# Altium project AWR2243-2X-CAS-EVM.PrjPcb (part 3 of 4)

## Sheet FE1_IO.schdoc: XDS110 Interface_1B
size 431 x 279 mm; Date: Not shown in title block; ApprovedBy: Not shown in title block; CheckedBy: Not shown in title block; Author: Not shown in title block; CompanyName: Not shown in title block; DrawnBy: B. Shaffer; Engineer: Not shown in title block; Organization: Not shown in title block; Address1: Not shown in title block; Address2: Not shown in title block; Address3: Not shown in title block; Address4: Not shown in title block; DocumentNumber: 7; Revision: Use project parameter SCH_Rev; SheetNumber: 7; SheetTotal: 17; PageSetup: Record=PageOptions¦CenterHorizontal=True¦CenterVertical=True¦PrintScale=1.00¦XCorrection=1.00¦YCorrection=1.00¦PrintKind=0¦BorderSize=5000000¦LeftOffset=0¦BottomOffset=0¦Orientation=2¦PaperLength=1000¦PaperWidth=1000¦Scale=100¦PaperSource=15¦PrintQuality=600¦MediaType=1¦DitherType=10¦PaperKind=Letter¦PrintScaleMode=1
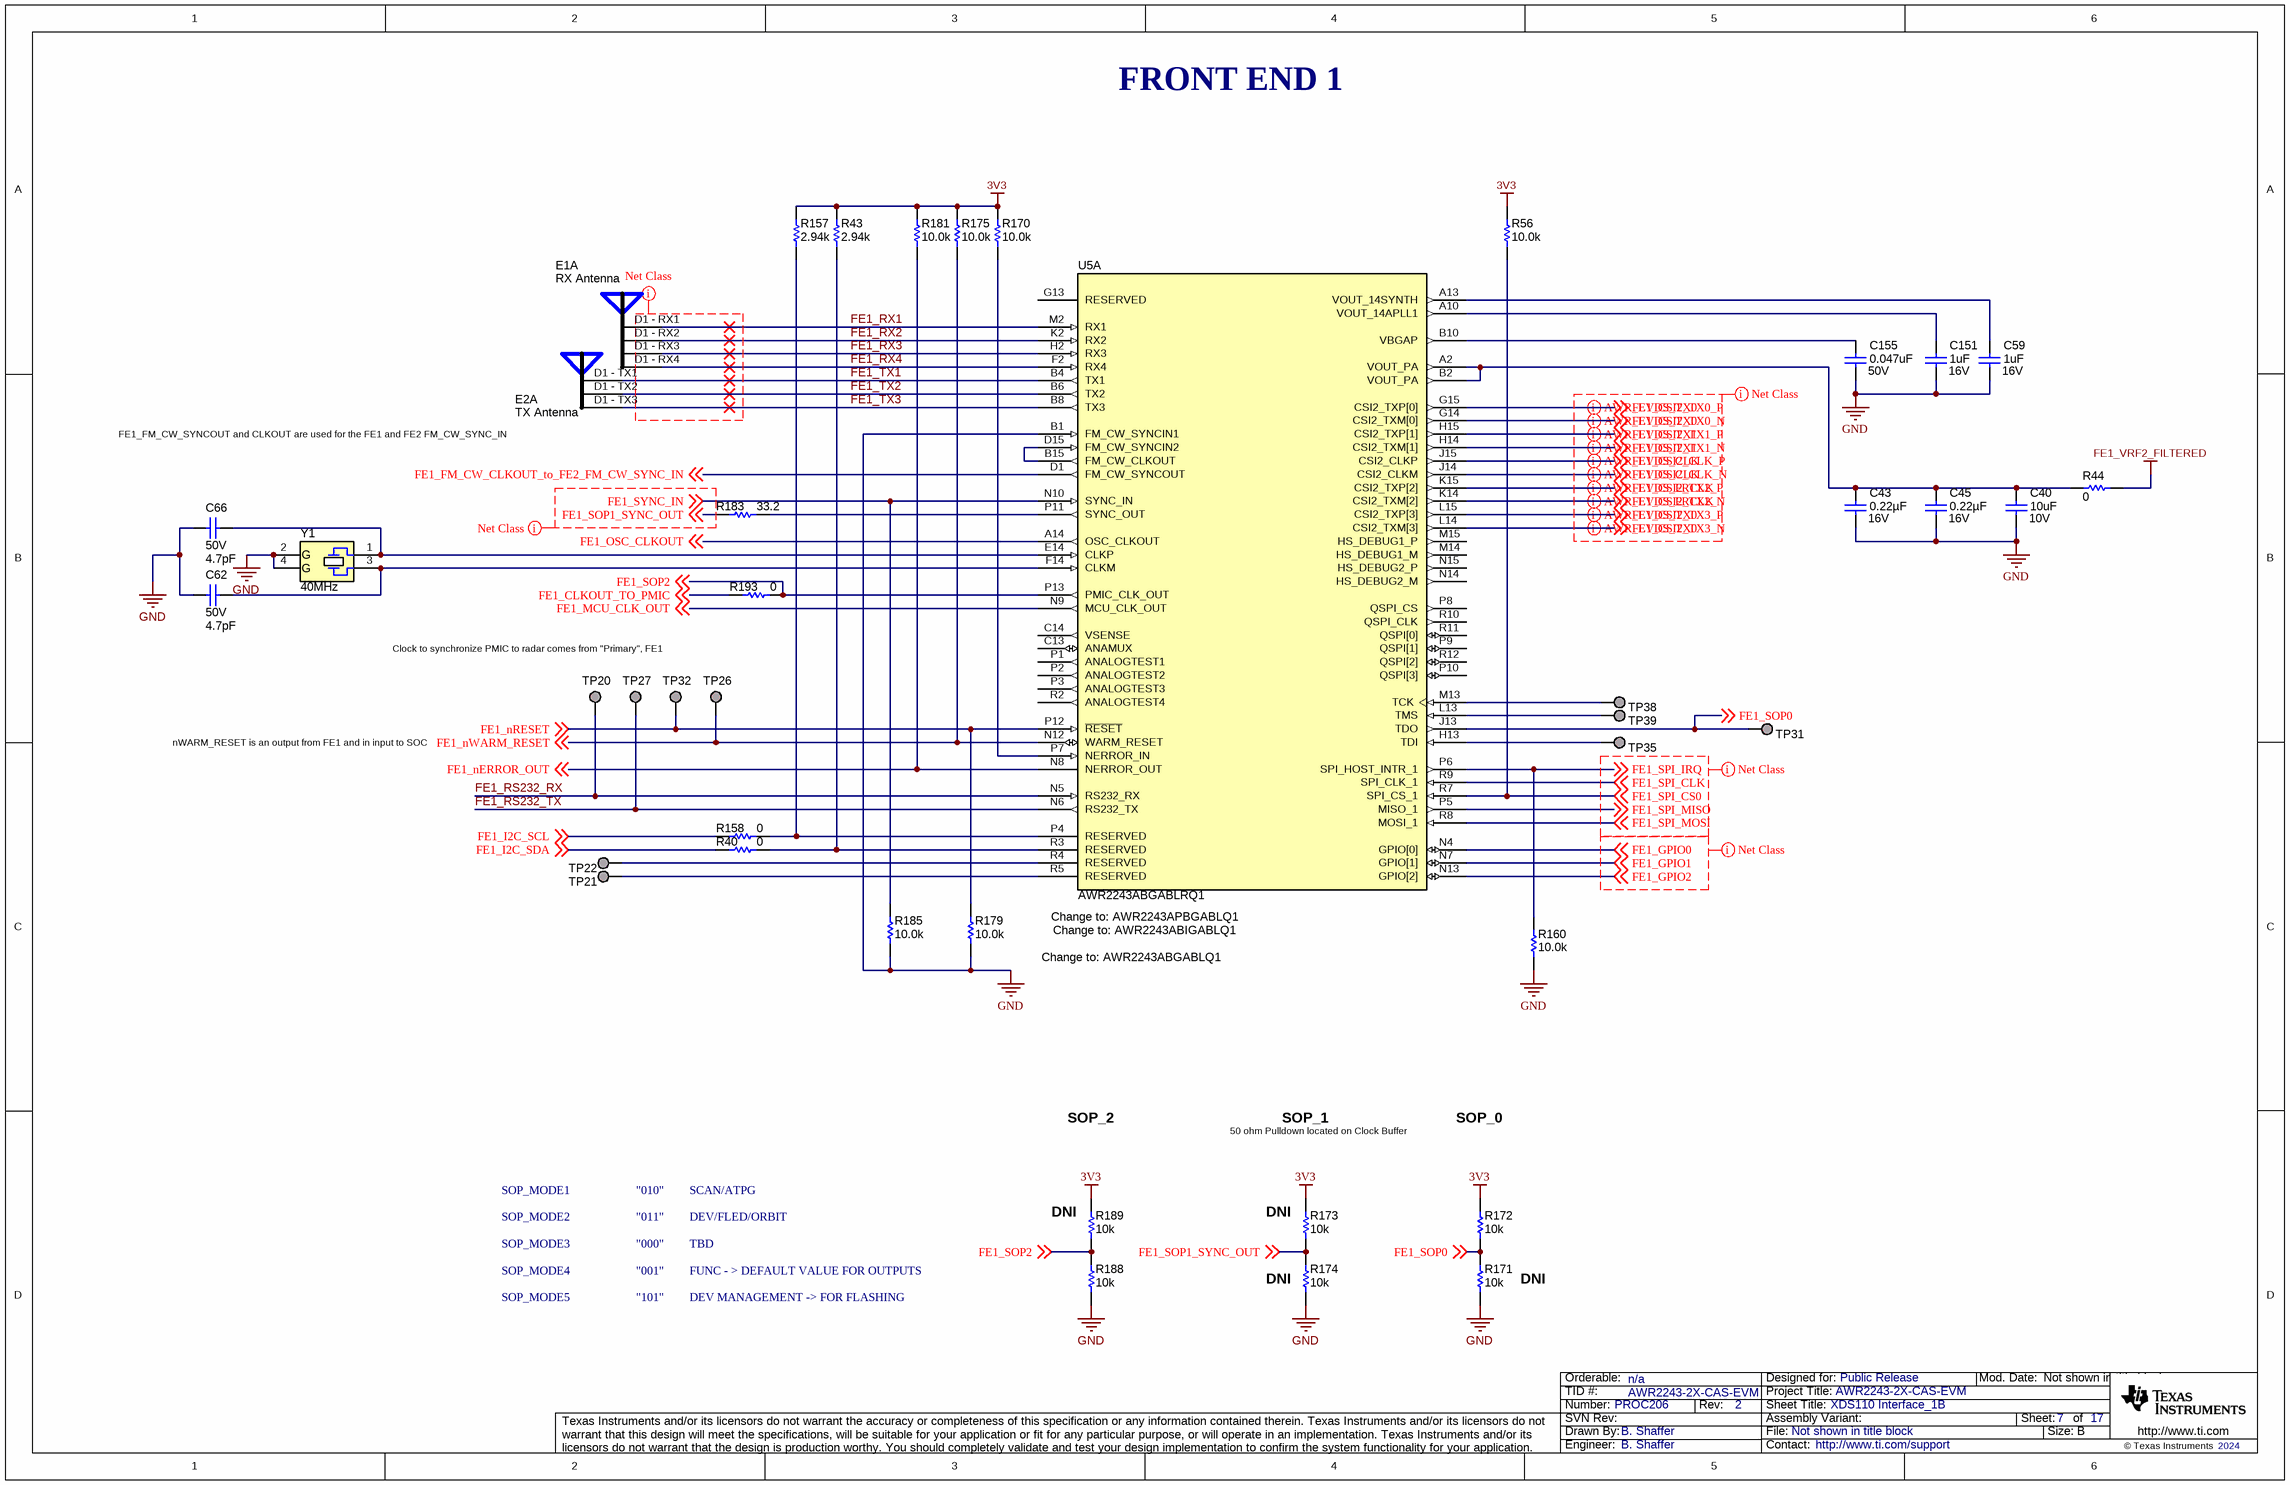
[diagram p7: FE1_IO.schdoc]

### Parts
(Parts that share a designator on the sheet are numbered #1, #2 ... from top to bottom, then left to right.)
C40  VDC_V: 10V  ValueDisplayed: 10uF  [0805_HV]  (hidden comment: GCM21BR71A106KE22L)
C43  VDC_V: 16V  ValueDisplayed: 0.22µF  [0402]  (hidden comment: GCM155R71C224KE02D)
C45  VDC_V: 16V  ValueDisplayed: 0.22µF  [0402L]  (hidden comment: GCM155R71C224KE02D)
C59  VDC_V: 16V  ValueDisplayed: 1uF  [0603]  (hidden comment: GCM188R71C105KA64D)
C62  VDC_V: 50V  ValueDisplayed: 4.7pF  [0402]  (hidden comment: GJM1555C1H4R7BB01D)
C66  VDC_V: 50V  ValueDisplayed: 4.7pF  [0402]  (hidden comment: GJM1555C1H4R7BB01D)
C151  VDC_V: 16V  ValueDisplayed: 1uF  [0603]  (hidden comment: GCM188R71C105KA64D)
C155  VDC_V: 50V  ValueDisplayed: 0.047uF  [0402]  (hidden comment: CGA2B3X7R1H473K050BB)
E1  RX Antenna  [RX Antenna]  (part A of 2)
E2  TX Antenna  [TX Antenna]  (part A of 2)
R40  ValueDisplayed: 0  [0402]  (hidden comment: CRCW04020000Z0ED)
R43  ValueDisplayed: 2.94k  [0402L]  (hidden comment: CRCW04022K94FKED)
R44  ValueDisplayed: 0  [0603]  (hidden comment: MCT06030Z0000ZP500)
R56  ValueDisplayed: 10.0k  [0402L]  (hidden comment: CRCW040210K0FKED)
R157  ValueDisplayed: 2.94k  [0402]  (hidden comment: CRCW04022K94FKED)
R158  ValueDisplayed: 0  [0402]  (hidden comment: CRCW04020000Z0ED)
R160  ValueDisplayed: 10.0k  [0402L]  (hidden comment: CRCW040210K0FKED)
R170  ValueDisplayed: 10.0k  [0402L]  (hidden comment: CRCW040210K0FKED)
R171  ValueDisplayed: 10k  [0402]  (hidden comment: CRCW040210K0JNED)
R172  ValueDisplayed: 10k  [0402]  (hidden comment: CRCW040210K0JNED)
R173  ValueDisplayed: 10k  [0402]  (hidden comment: CRCW040210K0JNED)
R174  ValueDisplayed: 10k  [0402]  (hidden comment: CRCW040210K0JNED)
R175  ValueDisplayed: 10.0k  [0402L]  (hidden comment: CRCW040210K0FKED)
R179  ValueDisplayed: 10.0k  [0402L]  (hidden comment: CRCW040210K0FKED)
R181  ValueDisplayed: 10.0k  [0402L]  (hidden comment: CRCW040210K0FKED)
R183  ValueDisplayed: 33.2  [0402S]  (hidden comment: CRCW040233R2FKED)
R185  ValueDisplayed: 10.0k  [0402L]  (hidden comment: CRCW040210K0FKED)
R188  ValueDisplayed: 10k  [0402]  (hidden comment: CRCW040210K0JNED)
R189  ValueDisplayed: 10k  [0402]  (hidden comment: CRCW040210K0JNED)
R193  ValueDisplayed: 0  [0402]  (hidden comment: CRCW04020000Z0ED)
TP20  TP_H0.45P0.75  [TP_H045P075]  (value not drawn)  (no BOM)
TP21  TP_H0.45P0.75  [TP_H045P075]  (value not drawn)  (no BOM)
TP22  TP_H0.45P0.75  [TP_H045P075]  (value not drawn)  (no BOM)
TP26  TP_H0.45P0.75  [TP_H045P075]  (value not drawn)  (no BOM)
TP27  TP_H0.45P0.75  [TP_H045P075]  (value not drawn)  (no BOM)
TP31  TP_H0.45P0.75  [TP_H045P075]  (value not drawn)  (no BOM)
TP32  TP_H0.45P0.75  [TP_H045P075]  (value not drawn)  (no BOM)
TP35  TP_H0.45P0.75  [TP_H045P075]  (value not drawn)  (no BOM)
TP38  TP_H0.45P0.75  [TP_H045P075]  (value not drawn)  (no BOM)
TP39  TP_H0.45P0.75  [TP_H045P075]  (value not drawn)  (no BOM)
U5#2  AWR2243ABGABLRQ1  [ABL0161A]  (part A of 2)
Y1  Frequency_Fixed: 40MHz  [Kyocera_CX3225SA]  (hidden comment: CX3225SA40000D0PTWCC)

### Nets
3V3: R43.2 R56.2 R157.2 R170.2 R172.2 R173.2 R175.2 R181.2 R189.2
FE1_VRF2_FILTERED: R44.2
GND: C40.2 C43.2 C45.2 C59.2 C62.2 C66.2 C151.2 C155.2 R160.1 R171.1 R174.1 R179.1 R185.1 R188.1 U5#2.B1(FM_CW_SYNCIN1) Y1.2(GND) Y1.4(GND)
FE1_CLKOUT_TO_PMIC: R193.2 ; off-sheet FE1_CLKOUT_TO_PMIC
FE1_CSI2_CLK_N: U5#2.J14(CSI2_CLKM) ; off-sheet FE1_CSI2_CLK_N
FE1_CSI2_CLK_P: U5#2.J15(CSI2_CLKP) ; off-sheet FE1_CSI2_CLK_P
FE1_CSI2_TX0_N: U5#2.G14(CSI2_TXM[0]) ; off-sheet FE1_CSI2_TX0_N
FE1_CSI2_TX0_P: U5#2.G15(CSI2_TXP[0]) ; off-sheet FE1_CSI2_TX0_P
FE1_CSI2_TX1_N: U5#2.H14(CSI2_TXM[1]) ; off-sheet FE1_CSI2_TX1_N
FE1_CSI2_TX1_P: U5#2.H15(CSI2_TXP[1]) ; off-sheet FE1_CSI2_TX1_P
FE1_CSI2_TX2_N: U5#2.K14(CSI2_TXM[2]) ; off-sheet FE1_CSI2_TX2_N
FE1_CSI2_TX2_P: U5#2.K15(CSI2_TXP[2]) ; off-sheet FE1_CSI2_TX2_P
FE1_CSI2_TX3_N: U5#2.L14(CSI2_TXM[3]) ; off-sheet FE1_CSI2_TX3_N
FE1_CSI2_TX3_P: U5#2.L15(CSI2_TXP[3]) ; off-sheet FE1_CSI2_TX3_P
FE1_FM_CW_CLKOUT_to_FE2_FM_CW_SYNC_IN: U5#2.D1(FM_CW_SYNCOUT) ; off-sheet FE1_FM_CW_CLKOUT_to_FE2_FM_CW_SYNC_IN
FE1_GPIO0: U5#2.N4(GPIO[0]) ; off-sheet FE1_GPIO0
FE1_GPIO1: U5#2.N7(GPIO[1]) ; off-sheet FE1_GPIO1
FE1_GPIO2: U5#2.N13(GPIO[2]) ; off-sheet FE1_GPIO2
FE1_I2C_SCL: R158.2 ; off-sheet FE1_I2C_SCL
FE1_I2C_SDA: R40.2 ; off-sheet FE1_I2C_SDA
FE1_MCU_CLK_OUT: U5#2.N9(MCU_CLK_OUT) ; off-sheet FE1_MCU_CLK_OUT
FE1_nERROR_OUT: R181.1 U5#2.N8(NERROR_OUT) ; off-sheet FE1_nERROR_OUT
FE1_nRESET: R179.2 TP32.1 U5#2.P12(~{RESET}) ; off-sheet FE1_nRESET
FE1_nWARM_RESET: R175.1 TP26.1 U5#2.N12(WARM_RESET) ; off-sheet FE1_nWARM_RESET
FE1_OSC_CLKOUT: U5#2.A14(OSC_CLKOUT) ; off-sheet FE1_OSC_CLKOUT
FE1_RS232_RX: TP20.1 U5#2.N5(RS232_RX)
FE1_RS232_TX: TP27.1 U5#2.N6(RS232_TX)
FE1_RX1: E1.D1_-_RX1 U5#2.M2(RX1)
FE1_RX2: E1.D1_-_RX2 U5#2.K2(RX2)
FE1_RX3: E1.D1_-_RX3 U5#2.H2(RX3)
FE1_RX4: E1.D1_-_RX4 U5#2.F2(RX4)
FE1_SOP0: R171.2 R172.1 TP31.1 U5#2.J13(TDO) ; off-sheet FE1_SOP0
FE1_SOP1_SYNC_OUT: R173.1 R174.2 R183.1 ; off-sheet FE1_SOP1_SYNC_OUT
FE1_SOP2: R188.2 R189.1 R193.1 U5#2.P13(PMIC_CLK_OUT) ; off-sheet FE1_SOP2
FE1_SPI_CLK: U5#2.R9(SPI_CLK_1) ; off-sheet FE1_SPI_CLK
FE1_SPI_CS0: R56.1 U5#2.R7(SPI_CS_1) ; off-sheet FE1_SPI_CS0
FE1_SPI_IRQ: R160.2 U5#2.P6(SPI_HOST_INTR_1) ; off-sheet FE1_SPI_IRQ
FE1_SPI_MISO: U5#2.P5(MISO_1) ; off-sheet FE1_SPI_MISO
FE1_SPI_MOSI: U5#2.R8(MOSI_1) ; off-sheet FE1_SPI_MOSI
FE1_SYNC_IN: R185.2 U5#2.N10(SYNC_IN) ; off-sheet FE1_SYNC_IN
FE1_TX1: E2.D1_-_TX1 U5#2.B4(TX1)
FE1_TX2: E2.D1_-_TX2 U5#2.B6(TX2)
FE1_TX3: E2.D1_-_TX3 U5#2.B8(TX3)
NetC40_1: C40.1 C43.1 C45.1 R44.1 U5#2.A2(VOUT_PA) U5#2.B2(VOUT_PA)
NetC59_1: C59.1 U5#2.A13(VOUT_14SYNTH)
NetC62_1: C62.1 U5#2.F14(CLKM) Y1.3
NetC66_1: C66.1 U5#2.E14(CLKP) Y1.1
NetC151_1: C151.1 U5#2.A10(VOUT_14APLL1)
NetC155_1: C155.1 U5#2.B10(VBGAP)
NetR40_1: R40.1 R43.1 U5#2.R3(RESERVED)
NetR157_1: R157.1 R158.1 U5#2.P4(RESERVED)
NetR170_1: R170.1 U5#2.P7(NERROR_IN)
NetR183_2: R183.2 U5#2.P11(SYNC_OUT)
NetTP21_1: TP21.1 U5#2.R5(RESERVED)
NetTP22_1: TP22.1 U5#2.R4(RESERVED)
NetTP35_1: TP35.1 U5#2.H13(TDI)
NetTP38_1: TP38.1 U5#2.M13(TCK)
NetTP39_1: TP39.1 U5#2.L13(TMS)
NetU5#2_B15: U5#2.B15(FM_CW_CLKOUT) U5#2.D15(FM_CW_SYNCIN2)

Not connected (* = marked no-connect by the designer): U5#2 C13(ANAMUX) C14(VSENSE) G13(RESERVED) M14(HS_DEBUG1_M) M15(HS_DEBUG1_P) N14(HS_DEBUG2_M) N15(HS_DEBUG2_P) P1(ANALOGTEST1) P2(ANALOGTEST2) P3(ANALOGTEST3) P8(QSPI_CS) P9(QSPI[1]) P10(QSPI[3]) R2(ANALOGTEST4) R10(QSPI_CLK) R11(QSPI[0]) R12(QSPI[2])

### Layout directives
net class RF: (no net found under the mark)
net class GENERAL: FE1_GPIO0, FE1_GPIO1, FE1_GPIO2, FE1_SOP1_SYNC_OUT, FE1_SYNC_IN
net class SPI: FE1_SPI_CLK, FE1_SPI_CS0, FE1_SPI_IRQ, FE1_SPI_MISO, FE1_SPI_MOSI
net class LVDS: FE1_CSI2_CLK_N, FE1_CSI2_CLK_P, FE1_CSI2_TX0_N, FE1_CSI2_TX0_P, FE1_CSI2_TX1_N, FE1_CSI2_TX1_P, FE1_CSI2_TX2_N, FE1_CSI2_TX2_P, FE1_CSI2_TX3_N, FE1_CSI2_TX3_P
differential pair: FE1_CSI2_CLK_N, FE1_CSI2_CLK_P, FE1_CSI2_TX0_N, FE1_CSI2_TX0_P, FE1_CSI2_TX1_N, FE1_CSI2_TX1_P, FE1_CSI2_TX2_N, FE1_CSI2_TX2_P, FE1_CSI2_TX3_N, FE1_CSI2_TX3_P

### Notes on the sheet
- FRONT END 1
- FE1_FM_CW_SYNCOUT and CLKOUT are used for the FE1 and FE2 FM_CW_SYNC_IN
- Clock to synchronize PMIC to radar comes from "Primary", FE1
- nWARM_RESET is an output from FE1 and in input to SOC
- (near U5#2) BAR MISSING?
- Change to: AWR2243ABGABLQ1
- (near U5#2) Change to: AWR2243APBGABLQ1
- (near U5#2) Change to: AWR2243ABIGABLQ1
- SOP_2
- SOP_1
- 50 ohm Pulldown located on Clock Buffer
- SOP_0
- SOP_MODE1
- SOP_MODE2
- "010"
- "011"
- SCAN/ATPG
- DEV/FLED/ORBIT
- (near R189) DNI
- (near R173) DNI
- SOP_MODE3
- SOP_MODE4
- SOP_MODE5
- "000"
- "001"
- "101"
- TBD
- FUNC - > DEFAULT VALUE FOR OUTPUTS
- DEV MANAGEMENT -> FOR FLASHING
- (near R174) DNI
- DNI

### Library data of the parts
C40 = CMP-0008017-2: CAP, CERM, 10 uF, 10 V, +/- 10%, X7R, 0805; Manufacturer: MuRata; TaMin_C: -55°C; Polarized: N; SizeAreaWB_mm2: 6.75; Value1: Unknown; U/M: EA; Value: 10uF; TaMax_C: 125°C; SizeZ_mm: 1.45; SizeX_mm: 2; SizeY_mm: 1.25; Cap_Case: 0805; SizeArea_mm2: 2.5; CompType: Capacitor; Cap_F: 10µF; AEC Category: Q200
C43 = CMP-0078265-1: CAP, CERM, 0.22 µF, 16 V,+/- 10%, X7R, AEC-Q200 Grade 1, 0402; Manufacturer: MuRata; TaMin_C: -55°C; Polarized: N; SizeAreaWB_mm2: 3; U/M: EA; Value: 0.22uF; TaMax_C: 125°C; SizeZ_mm: 0.6; SizeX_mm: 1; SizeY_mm: 0.5; CompType: Capacitor; AEC Qualified: Y; Cap_F: 220nF; AEC Category: Q200
C45 = CMP-0078265-1: CAP, CERM, 0.22 µF, 16 V,+/- 10%, X7R, AEC-Q200 Grade 1, 0402; Manufacturer: MuRata; TaMin_C: -55°C; Polarized: N; SizeAreaWB_mm2: 3; U/M: EA; Value: 0.22uF; TaMax_C: 125°C; SizeZ_mm: 0.6; SizeX_mm: 1; SizeY_mm: 0.5; Cap_Case: 0402; CompType: Capacitor; AEC Qualified: Y; Cap_F: 220nF; AEC Category: Q200
C59 C151 = CMP-0007136-5: CAP, CERM, 1 uF, 16 V, +/- 10%, X7R, AEC-Q200 Grade 1, 0603; Manufacturer: MuRata; TaMin_C: -55°C; Polarized: N; SizeAreaWB_mm2: 4.68; Value1: Unknown; U/M: EA; Value: 1uF; TaMax_C: 125°C; SizeZ_mm: 1; SizeX_mm: 1.6; SizeY_mm: 0.8; SizeArea_mm2: 1.28; CompType: Capacitor; AEC Qualified: Y; Cap_F: 1µF; AEC Category: Q200
C62 C66 = CMP-0006367-2: CAP, CERM, 4.7 pF, 50 V, +/- 2%, C0G/NP0, 0402; Manufacturer: MuRata; TaMin_C: -55°C; Polarized: N; SizeAreaWB_mm2: 3; Value1: Unknown; U/M: EA; Value: 4.7pF; TaMax_C: 125°C; SizeZ_mm: 0.6; SizeX_mm: 1; SizeY_mm: 0.5; AEC Category: Q200
C155 = CMP-0006330-2: CAP, CERM, 0.047 uF, 50 V, +/- 10%, X7R, AEC-Q200 Grade 1, 0402; Manufacturer: TDK; TaMin_C: -55°C; ESR_ohm: 0.06407; Polarized: N; SizeAreaWB_mm2: 3; Value1: 0.06407 ohm; U/M: EA; TaMax_C: 125°C; SizeZ_mm: 0.6; SizeX_mm: 1; SizeY_mm: 0.5; CompType: Capacitor; AEC Qualified: Y; Cap_F: 47nF; IRMS_A: 646.122mA; AEC Category: Q200
R40 R158 R193 = CMP-0026822-3: RES, 0, 5%, 0.063 W, AEC-Q200 Grade 0, 0402; Manufacturer: Vishay-Dale; Power_W: 63mW; TempCo: 200 ppm/C; Value_Code: 0000; Value: 0; EIA_Code: E24; SizeX_mm: 1; SizeY_mm: 0.5; SizeZ_mm: 0.6; Value2: 0.063W; AEC Qualified: Y; VDC_V: 50V; AEC Category: Q200
R43 = CMP-0026244-2: RES, 2.94 k, 1%, 0.063 W, AEC-Q200 Grade 0, 0402; Manufacturer: Vishay-Dale; Power_W: 63mW; TempCo: 100 ppm/C; Value_Code: 2k94; Value: 2.94k; EIA_Code: E96; SizeX_mm: 1; SizeY_mm: 0.5; SizeZ_mm: 0.6; Value2: 0.063W; CompType: Resistor; AEC Qualified: Y; VDC_V: 50V; AEC Category: Q200; AEC Grade: 0
R44 = CMP-0025884-3: RES, 0, 5%, 0.125 W, 0603; Manufacturer: Vishay/Beyschlag; Power_W: 125mW; TempCo: ppm/C; Value_Code: 0000; U/M: EA; Value: 0; EIA_Code: E24; SizeX_mm: 1.6; SizeY_mm: 0.8; SizeZ_mm: 1; Value2: 0.125W; SizeArea_mm2: 1.28; CompType: Resistor; AEC Qualified: N; AEC Category: Q200
R56 R160 R170 R175 R181 = CMP-0025958-3: RES, 10.0 k, 1%, 0.063 W, AEC-Q200 Grade 0, 0402; Manufacturer: Vishay-Dale; Power_W: 63mW; TempCo: 100 ppm/C; Value_Code: 10k0; Value: 10.0k; EIA_Code: E96; Res_ohm: 10k; SizeX_mm: 1; SizeY_mm: 0.5; SizeZ_mm: 0.6; Value2: 0.063W; AEC Qualified: Y; VDC_V: 50V; AEC Category: Q200; AEC Grade: 0
R157 = CMP-0026244-2: RES, 2.94 k, 1%, 0.063 W, AEC-Q200 Grade 0, 0402; Manufacturer: Vishay-Dale; Power_W: 63mW; TempCo: 100 ppm/C; Value_Code: 2k94; Value: 2.94k; EIA_Code: E96; SizeX_mm: 1; SizeY_mm: 0.5; SizeZ_mm: 0.6; Value2: 0.063W; AEC Qualified: Y; VDC_V: 50V; AEC Category: Q200; AEC Grade: 0
R171-R174 R188 R189 = CMP-0026825-4: RES, 10 k, 5%, 0.063 W, 0402; Manufacturer: Vishay-Dale; Power_W: 63mW; TempCo: 200 ppm/C; Value_Code: 10k0; U/M: EA; Value: 10k; EIA_Code: E24; SizeX_mm: 1; SizeY_mm: 0.5; SizeZ_mm: 0.6; Value2: 0.063W; VDC_V: 50V; AEC Category: Q200
R179 R185 = CMP-0025958-3: RES, 10.0 k, 1%, 0.063 W, AEC-Q200 Grade 0, 0402; Manufacturer: Vishay-Dale; Power_W: 63mW; TempCo: 100 ppm/C; Value_Code: 10k0; Value: 10.0k; EIA_Code: E96; Res_ohm: 10k; SizeX_mm: 1; SizeY_mm: 0.5; SizeZ_mm: 0.6; Value2: 0.063W; CompType: Resistor; AEC Qualified: Y; VDC_V: 50V; AEC Category: Q200; AEC Grade: 0
R183 = CMP-0026299-2: RES, 33.2, 1%, 0.063 W, AEC-Q200 Grade 0, 0402; Manufacturer: Vishay-Dale; Power_W: 63mW; TempCo: 100 ppm/C; Value_Code: 33R2; Value: 33.2; EIA_Code: E96; SizeX_mm: 1; SizeY_mm: 0.5; SizeZ_mm: 0.6; Value2: 0.063W; CompType: Resistor; AEC Qualified: Y; VDC_V: 50V; AEC Category: Q200; AEC Grade: 0
TP20-TP22 TP26 TP27 TP31 TP32 TP35 TP38 TP39 = CMP-0003719-1: Testpoint; Manufacturer: Texas Instruments; CompType: Pad
U5#2 = CMP-0082537-1: Single Chip 77 and 79 GHz FMCW Transceiver, ABL0161A (FCBGA-161); Alternate Manufacturer: Texas Instruments; SizeAreaWB_mm2: 153.76; Rating: Automotive; SizeZ_mm: 1.17; SizeX_mm: 10.4; SizeArea_mm2: 108.16; CompType: IC; AEC Qualified: Y; AEC Category: Q200
Y1 = CMP-0004694-2: Crystal, 40 MHz, 8pF, SMD; Manufacturer: Kyocera; TaMin_C: -40°C; Frequency Stability: +/-200ppm; SizeAreaWB_mm2: 14.7; U/M: EA; TaMax_C: 125°C; SizeZ_mm: 0.8; SizeX_mm: 2.5; SizeY_mm: 3.2; SizeArea_mm2: 8

## Sheet FE2_PWR.SchDoc
size 431 x 279 mm; Date: Not shown in title block; ApprovedBy: Not shown in title block; CheckedBy: Not shown in title block; Author: Not shown in title block; CompanyName: Not shown in title block; DrawnBy: B. Shaffer; Engineer: Not shown in title block; Organization: Not shown in title block; Address1: Not shown in title block; Address2: Not shown in title block; Address3: Not shown in title block; Address4: Not shown in title block; DocumentNumber: 8; Revision: Use project parameter SCH_Rev; SheetNumber: 8; SheetTotal: 17; PageSetup: Record=PageOptions¦CenterHorizontal=True¦CenterVertical=True¦PrintScale=1.00¦XCorrection=1.00¦YCorrection=1.00¦PrintKind=0¦BorderSize=5000000¦LeftOffset=0¦BottomOffset=0¦Orientation=2¦PaperLength=1000¦PaperWidth=1000¦Scale=100¦PaperSource=15¦PrintQuality=600¦MediaType=1¦DitherType=10¦PaperKind=Letter¦PrintScaleMode=1
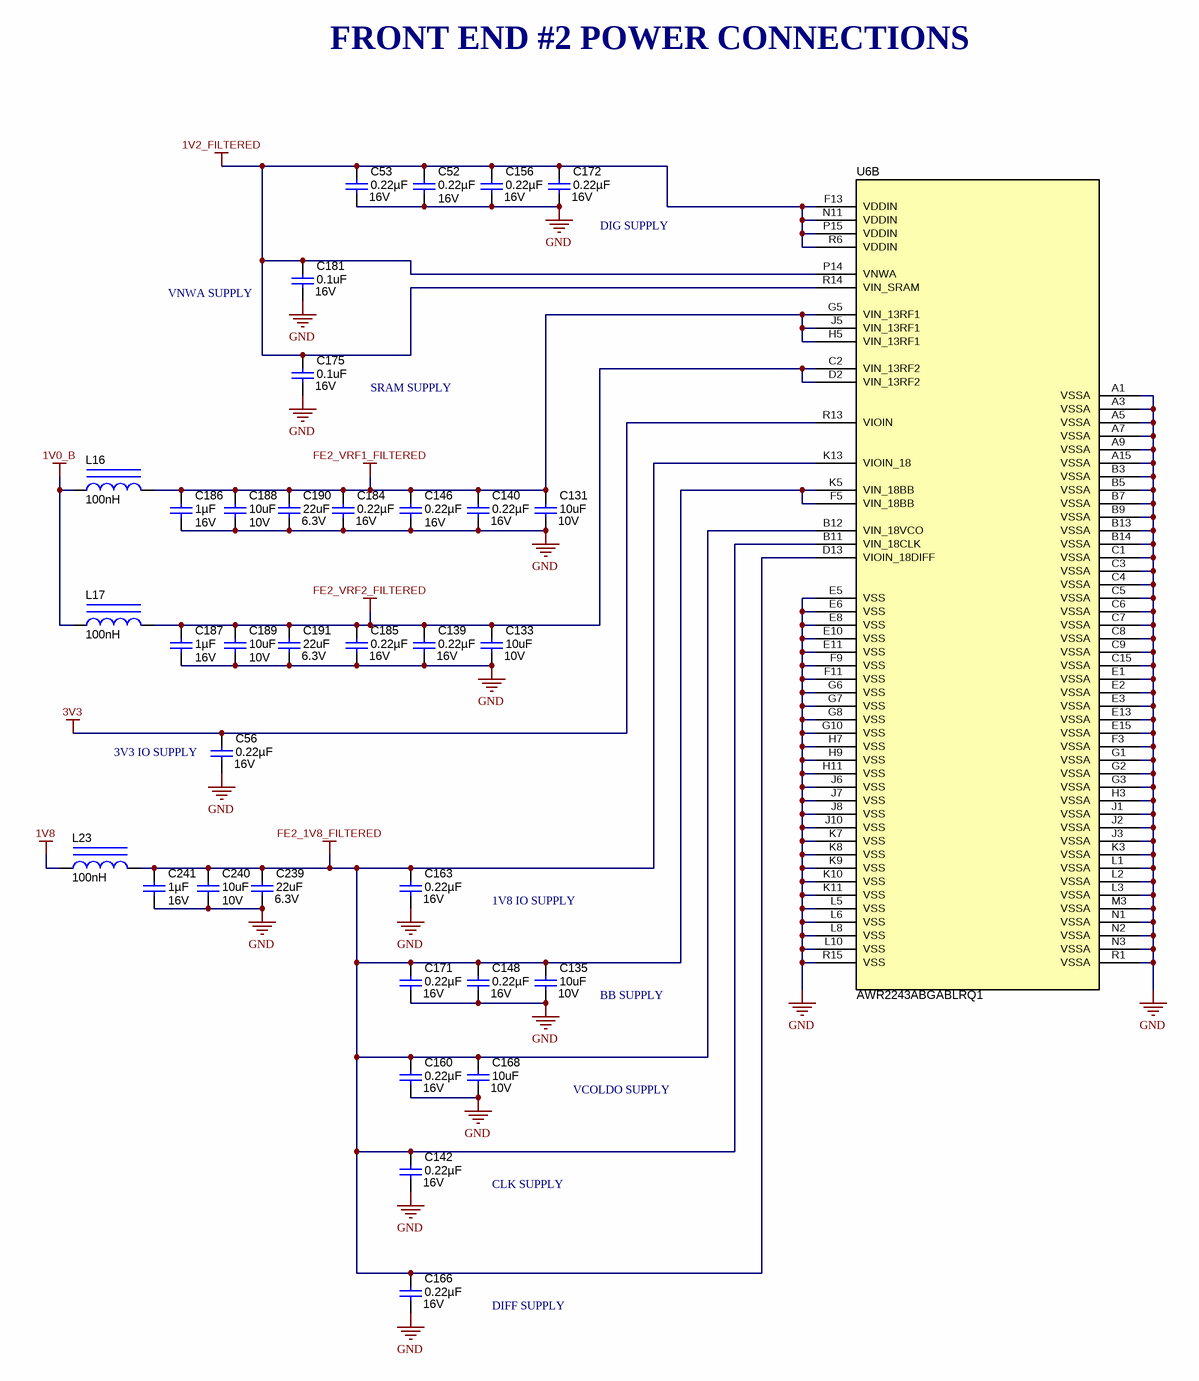
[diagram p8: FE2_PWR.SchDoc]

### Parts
(Parts that share a designator on the sheet are numbered #1, #2 ... from top to bottom, then left to right.)
C52  VDC_V: 16V  ValueDisplayed: 0.22µF  [0402L]  (hidden comment: GCM155R71C224KE02D)
C53  VDC_V: 16V  ValueDisplayed: 0.22µF  [0402L]  (hidden comment: GCM155R71C224KE02D)
C56  VDC_V: 16V  ValueDisplayed: 0.22µF  [0402L]  (hidden comment: GCM155R71C224KE02D)
C131  VDC_V: 10V  ValueDisplayed: 10uF  [0805_HV1]  (hidden comment: GCM21BR71A106KE22L)
C133  VDC_V: 10V  ValueDisplayed: 10uF  [0805]  (hidden comment: GCM21BR71A106KE22L)
C135  VDC_V: 10V  ValueDisplayed: 10uF  [0805_HV]  (hidden comment: GCM21BR71A106KE22L)
C139  VDC_V: 16V  ValueDisplayed: 0.22µF  [0402]  (hidden comment: GCM155R71C224KE02D)
C140  VDC_V: 16V  ValueDisplayed: 0.22µF  [0402L]  (hidden comment: GCM155R71C224KE02D)
C142  VDC_V: 16V  ValueDisplayed: 0.22µF  [0402L]  (hidden comment: GCM155R71C224KE02D)
C146  VDC_V: 16V  ValueDisplayed: 0.22µF  [0402L]  (hidden comment: GCM155R71C224KE02D)
C148  VDC_V: 16V  ValueDisplayed: 0.22µF  [0402]  (hidden comment: GCM155R71C224KE02D)
C156  VDC_V: 16V  ValueDisplayed: 0.22µF  [0402L]  (hidden comment: GCM155R71C224KE02D)
C160  VDC_V: 16V  ValueDisplayed: 0.22µF  [0402]  (hidden comment: GCM155R71C224KE02D)
C163  VDC_V: 16V  ValueDisplayed: 0.22µF  [0402]  (hidden comment: GCM155R71C224KE02D)
C166  VDC_V: 16V  ValueDisplayed: 0.22µF  [0402]  (hidden comment: GCM155R71C224KE02D)
C168  VDC_V: 10V  ValueDisplayed: 10uF  [0805_HV]  (hidden comment: GCM21BR71A106KE22L)
C171  VDC_V: 16V  ValueDisplayed: 0.22µF  [0402L]  (hidden comment: GCM155R71C224KE02D)
C172  VDC_V: 16V  ValueDisplayed: 0.22µF  [0402L]  (hidden comment: GCM155R71C224KE02D)
C175  VDC_V: 16V  ValueDisplayed: 0.1uF  [0402L]  (hidden comment: GCM155R71C104KA55D)
C181  VDC_V: 16V  ValueDisplayed: 0.1uF  [0402]  (hidden comment: GCM155R71C104KA55D)
C184  VDC_V: 16V  ValueDisplayed: 0.22µF  [0402L]  (hidden comment: GCM155R71C224KE02D)
C185  VDC_V: 16V  ValueDisplayed: 0.22µF  [0402L]  (hidden comment: GCM155R71C224KE02D)
C186  VDC_V: 16V  ValueDisplayed: 1µF  [0603S]  (hidden comment: GCM188R71C105KA64J)
C187  VDC_V: 16V  ValueDisplayed: 1µF  [0603S]  (hidden comment: GCM188R71C105KA64J)
C188  VDC_V: 10V  ValueDisplayed: 10uF  [0805L]  (hidden comment: GCM21BR71A106KE22L)
C189  VDC_V: 10V  ValueDisplayed: 10uF  [0805L]  (hidden comment: GCM21BR71A106KE22L)
C190  VDC_V: 6.3V  ValueDisplayed: 22uF  [0805]  (hidden comment: GCM21BD70J226ME36L)
C191  VDC_V: 6.3V  ValueDisplayed: 22uF  [0805]  (hidden comment: GCM21BD70J226ME36L)
C239  VDC_V: 6.3V  ValueDisplayed: 22uF  [0805]  (hidden comment: GCM21BD70J226ME36L)
C240  VDC_V: 10V  ValueDisplayed: 10uF  [0805L]  (hidden comment: GCM21BR71A106KE22L)
C241  VDC_V: 16V  ValueDisplayed: 1µF  [0603S]  (hidden comment: GCM188R71C105KA64J)
L16  ValueDisplayed: 100nH  [NLCV32]  (hidden comment: NLCV32T-R10M-EFRD)
L17  ValueDisplayed: 100nH  [NLCV32]  (hidden comment: NLCV32T-R10M-EFRD)
L23  ValueDisplayed: 100nH  [NLCV32]  (hidden comment: NLCV32T-R10M-EFRD)
U6#1  AWR2243ABGABLRQ1  [ABL0161A]  (part B of 2)

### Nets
1V0_B: L16.1 L17.1
1V2_FILTERED: C52.1 C53.1 C156.1 C172.1 C175.1 C181.1 U6#1.F13(VDDIN) U6#1.N11(VDDIN) U6#1.P14(VNWA) U6#1.P15(VDDIN) U6#1.R6(VDDIN) U6#1.R14(VIN_SRAM)
1V8: L23.1
3V3: C56.1 U6#1.R13(VIOIN)
FE2_1V8_FILTERED: C135.1 C142.1 C148.1 C160.1 C163.1 C166.1 C168.1 C171.1 C239.1 C240.1 C241.1 L23.2 U6#1.B11(VIN_18CLK) U6#1.B12(VIN_18VCO) U6#1.D13(VIOIN_18DIFF) U6#1.F5(VIN_18BB) U6#1.K5(VIN_18BB) U6#1.K13(VIOIN_18)
FE2_VRF1_FILTERED: C131.1 C140.1 C146.1 C184.1 C186.1 C188.1 C190.1 L16.2 U6#1.G5(VIN_13RF1) U6#1.H5(VIN_13RF1) U6#1.J5(VIN_13RF1)
FE2_VRF2_FILTERED: C133.1 C139.1 C185.1 C187.1 C189.1 C191.1 L17.2 U6#1.C2(VIN_13RF2) U6#1.D2(VIN_13RF2)
GND: C52.2 C53.2 C56.2 C131.2 C133.2 C135.2 C139.2 C140.2 C142.2 C146.2 C148.2 C156.2 C160.2 C163.2 C166.2 C168.2 C171.2 C172.2 C175.2 C181.2 C184.2 C185.2 C186.2 C187.2 C188.2 C189.2 C190.2 C191.2 C239.2 C240.2 C241.2 U6#1.A1(VSSA) U6#1.A3(VSSA) U6#1.A5(VSSA) U6#1.A7(VSSA) U6#1.A9(VSSA) U6#1.A15(VSSA) U6#1.B3(VSSA) U6#1.B5(VSSA) U6#1.B7(VSSA) U6#1.B9(VSSA) U6#1.B13(VSSA) U6#1.B14(VSSA) U6#1.C1(VSSA) U6#1.C3(VSSA) U6#1.C4(VSSA) U6#1.C5(VSSA) U6#1.C6(VSSA) U6#1.C7(VSSA) U6#1.C8(VSSA) U6#1.C9(VSSA) U6#1.C15(VSSA) U6#1.E1(VSSA) U6#1.E2(VSSA) U6#1.E3(VSSA) U6#1.E5(VSS) U6#1.E6(VSS) U6#1.E8(VSS) U6#1.E10(VSS) U6#1.E11(VSS) U6#1.E13(VSSA) U6#1.E15(VSSA) U6#1.F3(VSSA) U6#1.F9(VSS) U6#1.F11(VSS) U6#1.G1(VSSA) U6#1.G2(VSSA) U6#1.G3(VSSA) U6#1.G6(VSS) U6#1.G7(VSS) U6#1.G8(VSS) U6#1.G10(VSS) U6#1.H3(VSSA) U6#1.H7(VSS) U6#1.H9(VSS) U6#1.H11(VSS) U6#1.J1(VSSA) U6#1.J2(VSSA) U6#1.J3(VSSA) U6#1.J6(VSS) U6#1.J7(VSS) U6#1.J8(VSS) U6#1.J10(VSS) U6#1.K3(VSSA) U6#1.K7(VSS) U6#1.K8(VSS) U6#1.K9(VSS) U6#1.K10(VSS) U6#1.K11(VSS) U6#1.L1(VSSA) U6#1.L2(VSSA) U6#1.L3(VSSA) U6#1.L5(VSS) U6#1.L6(VSS) U6#1.L8(VSS) U6#1.L10(VSS) U6#1.M3(VSSA) U6#1.N1(VSSA) U6#1.N2(VSSA) U6#1.N3(VSSA) U6#1.R1(VSSA) U6#1.R15(VSS)

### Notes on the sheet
- FRONT END #2 POWER CONNECTIONS
- (near C172) DIG SUPPLY
- VNWA SUPPLY
- SRAM SUPPLY
- (near C56) 3V3 IO SUPPLY
- 1V8 IO SUPPLY
- BB SUPPLY
- VCOLDO SUPPLY
- CLK SUPPLY
- DIFF SUPPLY

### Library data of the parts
C52 C53 C56 C140 C142 C146 C156 C171 C172 C184 C185 = CMP-0078265-1: as C45 on sheet FE1_IO
C131 C135 C168 = CMP-0008017-2: as C40 on sheet FE1_IO
C133 = CMP-0008017-2: CAP, CERM, 10 uF, 10 V, +/- 10%, X7R, 0805; Manufacturer: MuRata; TaMin_C: -55°C; Polarized: N; SizeAreaWB_mm2: 6.75; Value1: Unknown; U/M: EA; Value: 10uF; TaMax_C: 125°C; SizeZ_mm: 1.45; SizeX_mm: 2; SizeY_mm: 1.25; SizeArea_mm2: 2.5; CompType: Capacitor; Cap_F: 10µF; AEC Category: Q200
C139 C148 C160 C163 C166 = CMP-0078265-1: as C43 on sheet FE1_IO
C175 = CMP-0006351-2: CAP, CERM, 0.1 uF, 16 V, +/- 10%, X7R, 0402; Manufacturer: MuRata; TaMin_C: -55°C; Polarized: N; SizeAreaWB_mm2: 3; Value1: Unknown; U/M: EA; Value: 0.1uF; TaMax_C: 125°C; SizeZ_mm: 0.6; SizeX_mm: 1; SizeY_mm: 0.5; Cap_Case: 0402; CompType: Capacitor; Cap_F: 100nF; AEC Category: Q200
C181 = CMP-0006351-2: CAP, CERM, 0.1 uF, 16 V, +/- 10%, X7R, 0402; Manufacturer: MuRata; TaMin_C: -55°C; Polarized: N; SizeAreaWB_mm2: 3; Value1: Unknown; U/M: EA; Value: 0.1uF; TaMax_C: 125°C; SizeZ_mm: 0.6; SizeX_mm: 1; SizeY_mm: 0.5; CompType: Capacitor; Cap_F: 100nF; AEC Category: Q200
C186 C187 C241 = CMP-0079154-1: CAP, CERM, 1 µF, 16 V,+/- 10%, X7R, AEC-Q200 Grade 1, 0603; Manufacturer: MuRata; SizeAreaWB_mm2: 4.68; SizeArea_mm2: 1.28; AEC Qualified: Y; AEC Category: Q200; Value: 1uF; TaMax_C: 125°C; SizeZ_mm: 1; Polarized: N; TaMin_C: -55°C; SizeY_mm: 0.8; U/M: EA; SizeX_mm: 1.6; Cap_Case: 0603
C188 C189 C240 = CMP-0008017-2: CAP, CERM, 10 uF, 10 V, +/- 10%, X7R, 0805; Manufacturer: MuRata; TaMin_C: -55°C; Polarized: N; SizeAreaWB_mm2: 6.75; Value1: Unknown; U/M: EA; Value: 10uF; TaMax_C: 125°C; SizeZ_mm: 1.45; SizeX_mm: 2; SizeY_mm: 1.25; Cap_Case: 0805; SizeArea_mm2: 2.5; Cap_F: 10µF; AEC Category: Q200
C190 C191 C239 = CMP-0008015-1: CAP, CERM, 22 uF, 6.3 V, +/- 20%, X7T, AEC-Q200 Grade 1, 0805; Manufacturer: MuRata; TaMin_C: -55°C; Polarized: N; SizeAreaWB_mm2: 6.75; Value1: Unknown; U/M: EA; Value: 22uF; TaMax_C: 125°C; SizeZ_mm: 1.45; SizeX_mm: 2; SizeY_mm: 1.25; SizeArea_mm2: 2.5; CompType: Capacitor; AEC Qualified: Y; Cap_F: 22µF; AEC Grade: 1; AEC Category: Q200
L16 L17 L23 = CMP-0083745-1: Inductor, Wirewound, Ferrite, 100 nH, 2.85 A, 0.024 ohm, AEC-Q200 Grade 1, SMD; Manufacturer: TDK; Isat: 2.85A @ 10% inductance drop; Irms: 2.85A @ 40C rise; SizeAreaWB_mm2: 13.44; DCR_ohm: 0.024; Value: 100nH; Imax_A: 2.85A; SizeZ_mm: 2.5; SizeX_mm: 3.2; SizeY_mm: 2.2; SizeArea_mm2: 7.04; AEC Qualified: Y; AEC Grade: 1; AEC Category: Q200
U6#1 = CMP-0082537-1: as U5#2 on sheet FE1_IO

## Sheet FE2_IO.schdoc
size 431 x 279 mm; Date: Not shown in title block; ApprovedBy: Not shown in title block; CheckedBy: Not shown in title block; Author: Not shown in title block; CompanyName: Not shown in title block; DrawnBy: B. Shaffer; Engineer: Not shown in title block; Organization: Not shown in title block; Address1: Not shown in title block; Address2: Not shown in title block; Address3: Not shown in title block; Address4: Not shown in title block; DocumentNumber: 9; Revision: Use project parameter SCH_Rev; SheetNumber: 9; SheetTotal: 17; PageSetup: Record=PageOptions¦CenterHorizontal=True¦CenterVertical=True¦PrintScale=1.00¦XCorrection=1.00¦YCorrection=1.00¦PrintKind=0¦BorderSize=5000000¦LeftOffset=0¦BottomOffset=0¦Orientation=2¦PaperLength=1000¦PaperWidth=1000¦Scale=100¦PaperSource=15¦PrintQuality=600¦MediaType=1¦DitherType=10¦PaperKind=Letter¦PrintScaleMode=1
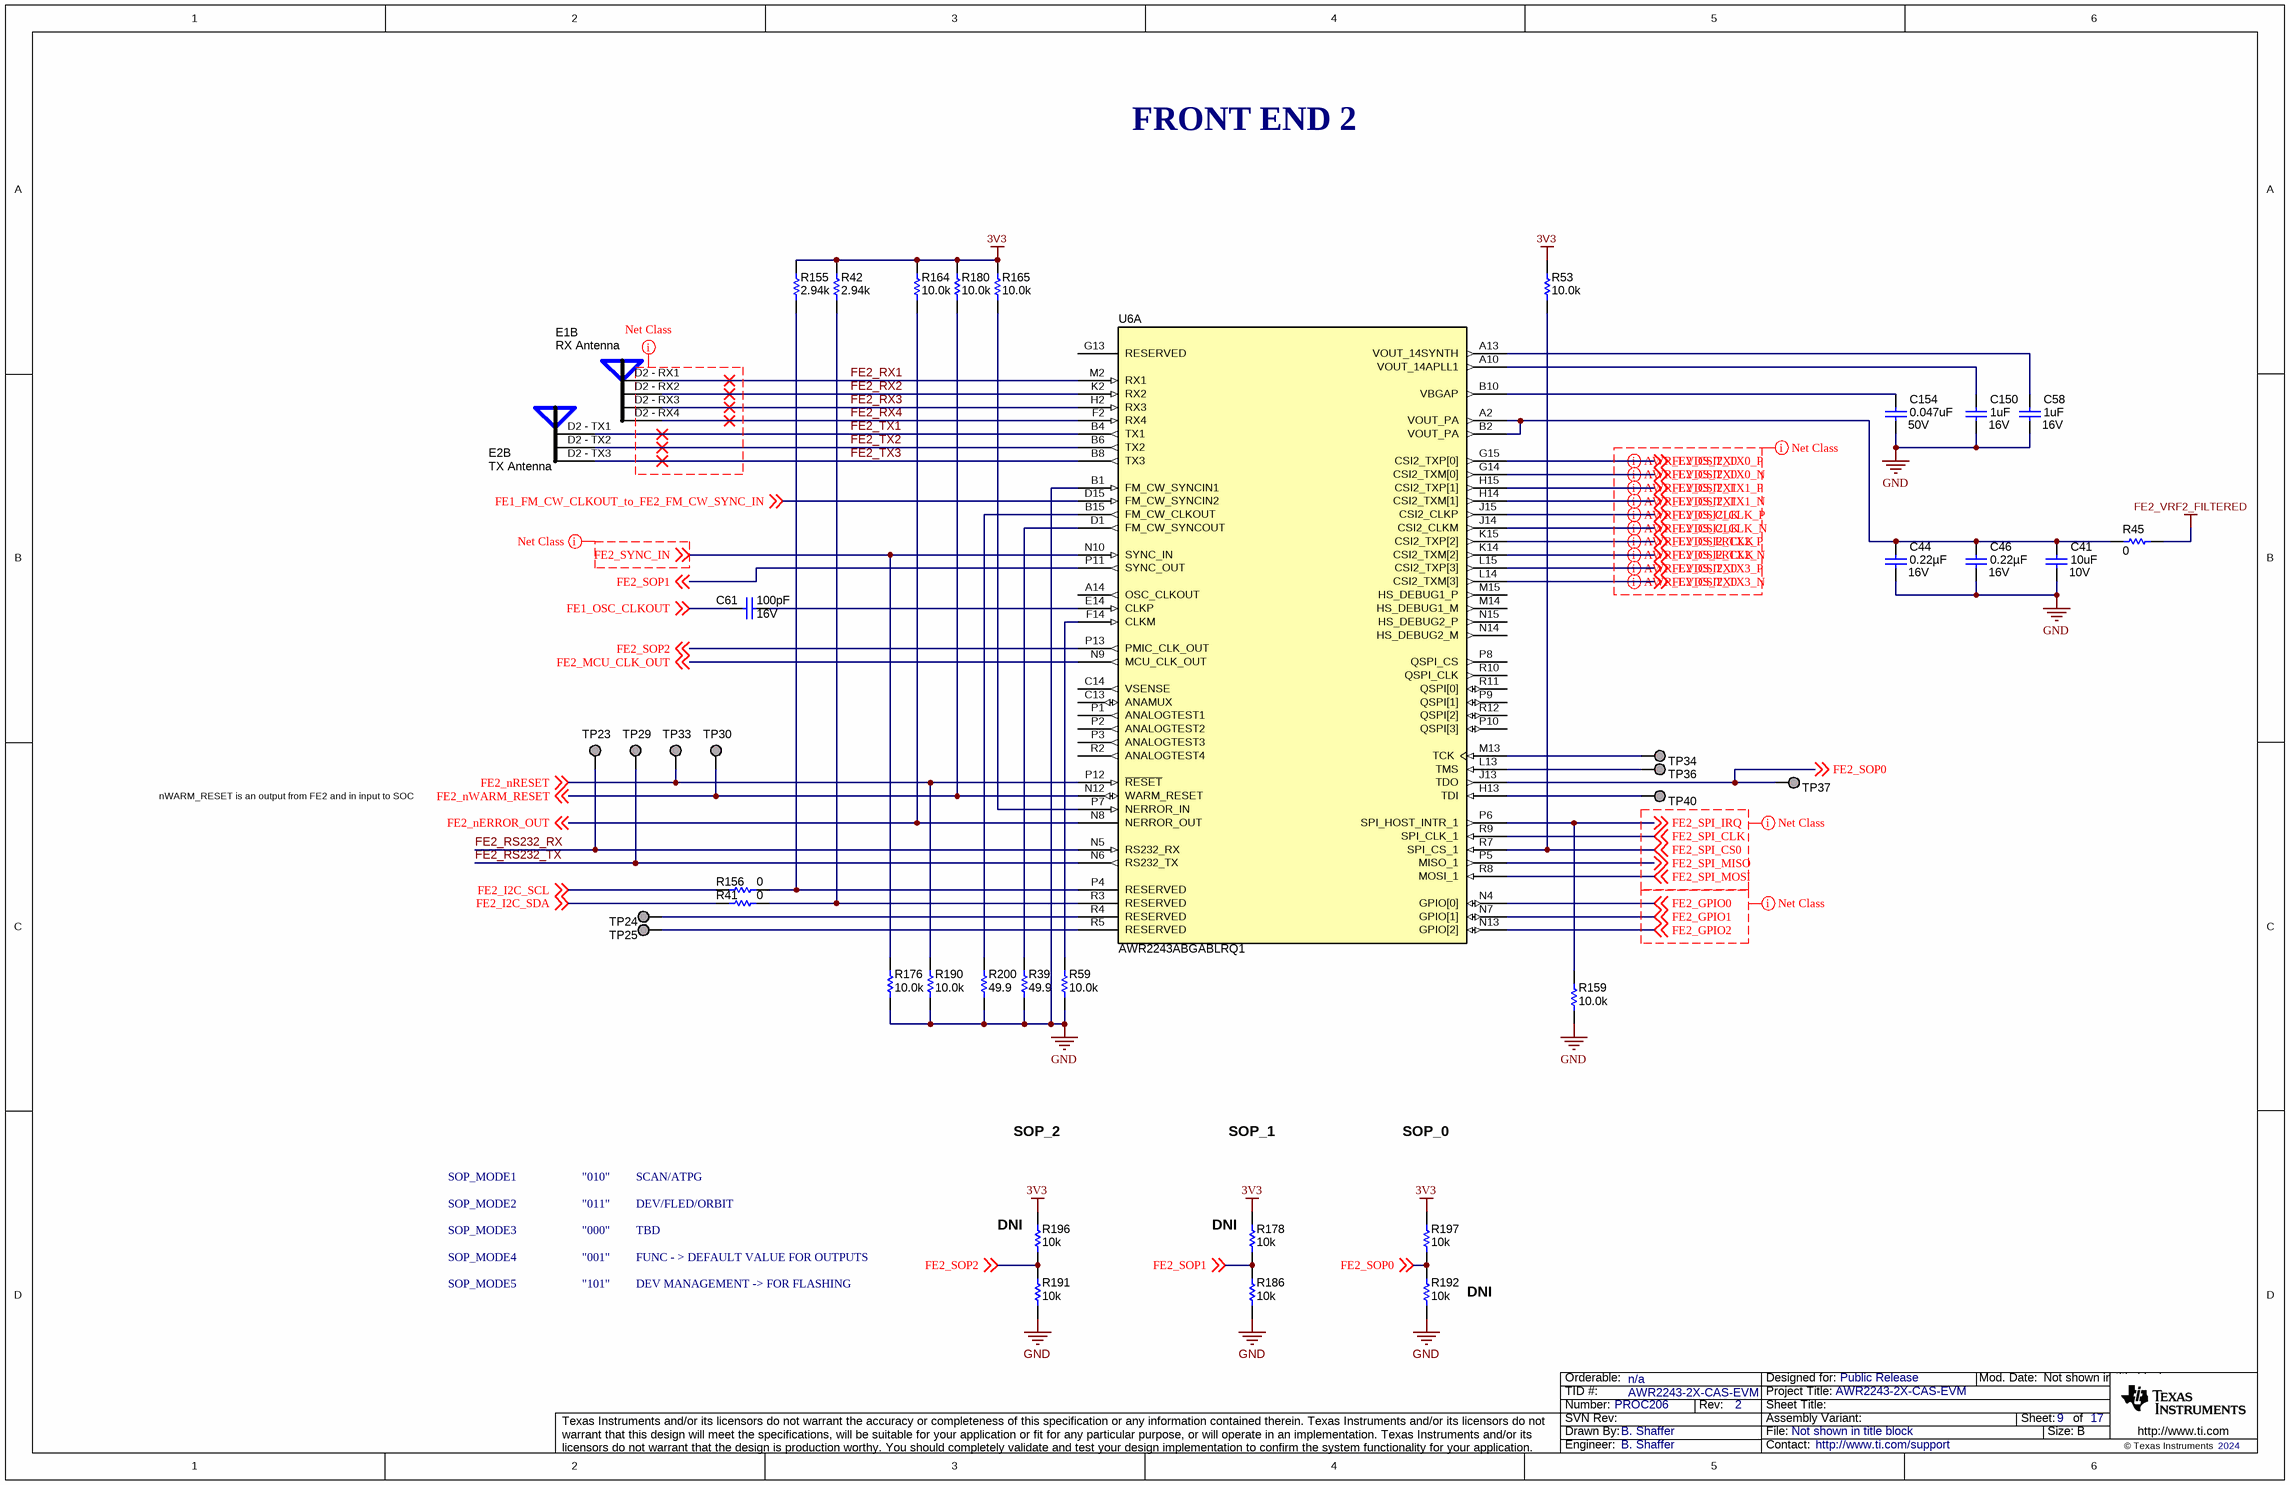
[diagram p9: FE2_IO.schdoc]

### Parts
(Parts that share a designator on the sheet are numbered #1, #2 ... from top to bottom, then left to right.)
C41  VDC_V: 10V  ValueDisplayed: 10uF  [0805_HV]  (hidden comment: GCM21BR71A106KE22L)
C44  VDC_V: 16V  ValueDisplayed: 0.22µF  [0402]  (hidden comment: GCM155R71C224KE02D)
C46  VDC_V: 16V  ValueDisplayed: 0.22µF  [0402L]  (hidden comment: GCM155R71C224KE02D)
C58  VDC_V: 16V  ValueDisplayed: 1uF  [0603]  (hidden comment: GCM188R71C105KA64D)
C61  VDC_V: 16V  ValueDisplayed: 100pF  [0402]  (hidden comment: 0402YC101KAT2A)
C150  VDC_V: 16V  ValueDisplayed: 1uF  [0603]  (hidden comment: GCM188R71C105KA64D)
C154  VDC_V: 50V  ValueDisplayed: 0.047uF  [0402]  (hidden comment: CGA2B3X7R1H473K050BB)
E1  RX Antenna  [RX Antenna]  (part B of 2)
E2  TX Antenna  [TX Antenna]  (part B of 2)
R39  ValueDisplayed: 49.9  [0402]  (hidden comment: CRCW040249R9FKED)
R41  ValueDisplayed: 0  [0402]  (hidden comment: CRCW04020000Z0ED)
R42  ValueDisplayed: 2.94k  [0402]  (hidden comment: CRCW04022K94FKED)
R45  ValueDisplayed: 0  [0603]  (hidden comment: MCT06030Z0000ZP500)
R53  ValueDisplayed: 10.0k  [0402L]  (hidden comment: CRCW040210K0FKED)
R59  ValueDisplayed: 10.0k  [0402L]  (hidden comment: CRCW040210K0FKED)
R155  ValueDisplayed: 2.94k  [0402]  (hidden comment: CRCW04022K94FKED)
R156  ValueDisplayed: 0  [0402]  (hidden comment: CRCW04020000Z0ED)
R159  ValueDisplayed: 10.0k  [0402L]  (hidden comment: CRCW040210K0FKED)
R164  ValueDisplayed: 10.0k  [0402L]  (hidden comment: CRCW040210K0FKED)
R165  ValueDisplayed: 10.0k  [0402L]  (hidden comment: CRCW040210K0FKED)
R176  ValueDisplayed: 10.0k  [0402L]  (hidden comment: CRCW040210K0FKED)
R178  ValueDisplayed: 10k  [0402]  (hidden comment: CRCW040210K0JNED)
R180  ValueDisplayed: 10.0k  [0402L]  (hidden comment: CRCW040210K0FKED)
R186  ValueDisplayed: 10k  [0402]  (hidden comment: CRCW040210K0JNED)
R190  ValueDisplayed: 10.0k  [0402L]  (hidden comment: CRCW040210K0FKED)
R191  ValueDisplayed: 10k  [0402]  (hidden comment: CRCW040210K0JNED)
R192  ValueDisplayed: 10k  [0402]  (hidden comment: CRCW040210K0JNED)
R196  ValueDisplayed: 10k  [0402]  (hidden comment: CRCW040210K0JNED)
R197  ValueDisplayed: 10k  [0402]  (hidden comment: CRCW040210K0JNED)
R200  ValueDisplayed: 49.9  [0402]  (hidden comment: CRCW040249R9FKED)
TP23  TP_H0.45P0.75  [TP_H045P075]  (value not drawn)  (no BOM)
TP24  TP_H0.45P0.75  [TP_H045P075]  (value not drawn)  (no BOM)
TP25  TP_H0.45P0.75  [TP_H045P075]  (value not drawn)  (no BOM)
TP29  TP_H0.45P0.75  [TP_H045P075]  (value not drawn)  (no BOM)
TP30  TP_H0.45P0.75  [TP_H045P075]  (value not drawn)  (no BOM)
TP33  TP_H0.45P0.75  [TP_H045P075]  (value not drawn)  (no BOM)
TP34  TP_H0.45P0.75  [TP_H045P075]  (value not drawn)  (no BOM)
TP36  TP_H0.45P0.75  [TP_H045P075]  (value not drawn)  (no BOM)
TP37  TP_H0.45P0.75  [TP_H045P075]  (value not drawn)  (no BOM)
TP40  TP_H0.45P0.75  [TP_H045P075]  (value not drawn)  (no BOM)
U6#2  AWR2243ABGABLRQ1  [ABL0161A]  (part A of 2)

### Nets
3V3: R42.2 R53.2 R155.2 R164.2 R165.2 R178.2 R180.2 R196.2 R197.2
FE2_VRF2_FILTERED: R45.2
GND: C41.2 C44.2 C46.2 C58.2 C150.2 C154.2 R39.1 R59.1 R159.1 R176.1 R186.1 R190.1 R191.1 R192.1 R200.1 U6#2.B1(FM_CW_SYNCIN1)
FE1_FM_CW_CLKOUT_to_FE2_FM_CW_SYNC_IN: U6#2.D15(FM_CW_SYNCIN2) ; off-sheet FE1_FM_CW_CLKOUT_to_FE2_FM_CW_SYNC_IN
FE1_OSC_CLKOUT: C61.2 ; off-sheet FE1_OSC_CLKOUT
FE2_CSI2_CLK_N: U6#2.J14(CSI2_CLKM) ; off-sheet FE2_CSI2_CLK_N
FE2_CSI2_CLK_P: U6#2.J15(CSI2_CLKP) ; off-sheet FE2_CSI2_CLK_P
FE2_CSI2_TX0_N: U6#2.G14(CSI2_TXM[0]) ; off-sheet FE2_CSI2_TX0_N
FE2_CSI2_TX0_P: U6#2.G15(CSI2_TXP[0]) ; off-sheet FE2_CSI2_TX0_P
FE2_CSI2_TX1_N: U6#2.H14(CSI2_TXM[1]) ; off-sheet FE2_CSI2_TX1_N
FE2_CSI2_TX1_P: U6#2.H15(CSI2_TXP[1]) ; off-sheet FE2_CSI2_TX1_P
FE2_CSI2_TX2_N: U6#2.K14(CSI2_TXM[2]) ; off-sheet FE2_CSI2_TX2_N
FE2_CSI2_TX2_P: U6#2.K15(CSI2_TXP[2]) ; off-sheet FE2_CSI2_TX2_P
FE2_CSI2_TX3_N: U6#2.L14(CSI2_TXM[3]) ; off-sheet FE2_CSI2_TX3_N
FE2_CSI2_TX3_P: U6#2.L15(CSI2_TXP[3]) ; off-sheet FE2_CSI2_TX3_P
FE2_GPIO0: U6#2.N4(GPIO[0]) ; off-sheet FE2_GPIO0
FE2_GPIO1: U6#2.N7(GPIO[1]) ; off-sheet FE2_GPIO1
FE2_GPIO2: U6#2.N13(GPIO[2]) ; off-sheet FE2_GPIO2
FE2_I2C_SCL: R156.2 ; off-sheet FE2_I2C_SCL
FE2_I2C_SDA: R41.2 ; off-sheet FE2_I2C_SDA
FE2_MCU_CLK_OUT: U6#2.N9(MCU_CLK_OUT) ; off-sheet FE2_MCU_CLK_OUT
FE2_nERROR_OUT: R164.1 U6#2.N8(NERROR_OUT) ; off-sheet FE2_nERROR_OUT
FE2_nRESET: R190.2 TP33.1 U6#2.P12(~{RESET}) ; off-sheet FE2_nRESET
FE2_nWARM_RESET: R180.1 TP30.1 U6#2.N12(WARM_RESET) ; off-sheet FE2_nWARM_RESET
FE2_RS232_RX: TP23.1 U6#2.N5(RS232_RX)
FE2_RS232_TX: TP29.1 U6#2.N6(RS232_TX)
FE2_RX1: E1.D2_-_RX1 U6#2.M2(RX1)
FE2_RX2: E1.D2_-_RX2 U6#2.K2(RX2)
FE2_RX3: E1.D2_-_RX3 U6#2.H2(RX3)
FE2_RX4: E1.D2_-_RX4 U6#2.F2(RX4)
FE2_SOP0: R192.2 R197.1 TP37.1 U6#2.J13(TDO) ; off-sheet FE2_SOP0
FE2_SOP1: R178.1 R186.2 U6#2.P11(SYNC_OUT) ; off-sheet FE2_SOP1
FE2_SOP2: R191.2 R196.1 U6#2.P13(PMIC_CLK_OUT) ; off-sheet FE2_SOP2
FE2_SPI_CLK: U6#2.R9(SPI_CLK_1) ; off-sheet FE2_SPI_CLK
FE2_SPI_CS0: R53.1 U6#2.R7(SPI_CS_1) ; off-sheet FE2_SPI_CS0
FE2_SPI_IRQ: R159.2 U6#2.P6(SPI_HOST_INTR_1) ; off-sheet FE2_SPI_IRQ
FE2_SPI_MISO: U6#2.P5(MISO_1) ; off-sheet FE2_SPI_MISO
FE2_SPI_MOSI: U6#2.R8(MOSI_1) ; off-sheet FE2_SPI_MOSI
FE2_SYNC_IN: R176.2 U6#2.N10(SYNC_IN) ; off-sheet FE2_SYNC_IN
FE2_TX1: E2.D2_-_TX1 U6#2.B4(TX1)
FE2_TX2: E2.D2_-_TX2 U6#2.B6(TX2)
FE2_TX3: E2.D2_-_TX3 U6#2.B8(TX3)
NetC41_1: C41.1 C44.1 C46.1 R45.1 U6#2.A2(VOUT_PA) U6#2.B2(VOUT_PA)
NetC58_1: C58.1 U6#2.A13(VOUT_14SYNTH)
NetC61_1: C61.1 U6#2.E14(CLKP)
NetC150_1: C150.1 U6#2.A10(VOUT_14APLL1)
NetC154_1: C154.1 U6#2.B10(VBGAP)
NetR39_2: R39.2 U6#2.D1(FM_CW_SYNCOUT)
NetR41_1: R41.1 R42.1 U6#2.R3(RESERVED)
NetR59_2: R59.2 U6#2.F14(CLKM)
NetR155_1: R155.1 R156.1 U6#2.P4(RESERVED)
NetR165_1: R165.1 U6#2.P7(NERROR_IN)
NetR200_2: R200.2 U6#2.B15(FM_CW_CLKOUT)
NetTP24_1: TP24.1 U6#2.R4(RESERVED)
NetTP25_1: TP25.1 U6#2.R5(RESERVED)
NetTP34_1: TP34.1 U6#2.M13(TCK)
NetTP36_1: TP36.1 U6#2.L13(TMS)
NetTP40_1: TP40.1 U6#2.H13(TDI)

Not connected (* = marked no-connect by the designer): U6#2 A14(OSC_CLKOUT) C13(ANAMUX) C14(VSENSE) G13(RESERVED) M14(HS_DEBUG1_M) M15(HS_DEBUG1_P) N14(HS_DEBUG2_M) N15(HS_DEBUG2_P) P1(ANALOGTEST1) P2(ANALOGTEST2) P3(ANALOGTEST3) P8(QSPI_CS) P9(QSPI[1]) P10(QSPI[3]) R2(ANALOGTEST4) R10(QSPI_CLK) R11(QSPI[0]) R12(QSPI[2])

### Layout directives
net class RF: (no net found under the mark)
net class GENERAL: FE2_GPIO0, FE2_GPIO1, FE2_GPIO2, FE2_SYNC_IN
net class SPI: FE2_SPI_CLK, FE2_SPI_CS0, FE2_SPI_IRQ, FE2_SPI_MISO, FE2_SPI_MOSI
net class LVDS: FE2_CSI2_CLK_N, FE2_CSI2_CLK_P, FE2_CSI2_TX0_N, FE2_CSI2_TX0_P, FE2_CSI2_TX1_N, FE2_CSI2_TX1_P, FE2_CSI2_TX2_N, FE2_CSI2_TX2_P, FE2_CSI2_TX3_N, FE2_CSI2_TX3_P
differential pair: FE2_CSI2_CLK_N, FE2_CSI2_CLK_P, FE2_CSI2_TX0_N, FE2_CSI2_TX0_P, FE2_CSI2_TX1_N, FE2_CSI2_TX1_P, FE2_CSI2_TX2_N, FE2_CSI2_TX2_P, FE2_CSI2_TX3_N, FE2_CSI2_TX3_P

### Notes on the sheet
- FRONT END 2
- nWARM_RESET is an output from FE2 and in input to SOC
- (near U6#2) BAR MISSING?
- SOP_2
- SOP_1
- SOP_0
- SOP_MODE1
- SOP_MODE2
- SOP_MODE3
- "010"
- "011"
- "000"
- SCAN/ATPG
- DEV/FLED/ORBIT
- TBD
- (near R196) DNI
- (near R178) DNI
- SOP_MODE4
- SOP_MODE5
- "001"
- "101"
- FUNC - > DEFAULT VALUE FOR OUTPUTS
- DEV MANAGEMENT -> FOR FLASHING
- DNI

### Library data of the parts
C41 = CMP-0008017-2: as C40 on sheet FE1_IO
C44 = CMP-0078265-1: as C43 on sheet FE1_IO
C46 = CMP-0078265-1: as C45 on sheet FE1_IO
C58 C150 = CMP-0007136-5: as C59 on sheet FE1_IO
C61 = CMP-0006200-2: CAP, CERM, 100 pF, 16 V, +/- 10%, X7R, 0402; Manufacturer: AVX; TaMin_C: -55°C; Polarized: N; SizeAreaWB_mm2: 3; Value1: Unknown; U/M: EA; Value: 100pF; TaMax_C: 125°C; SizeZ_mm: 0.6; SizeX_mm: 1; SizeY_mm: 0.5; AEC Category: Q200
C154 = CMP-0006330-2: as C155 on sheet FE1_IO
R39 R200 = CMP-0026404-2: RES, 49.9, 1%, 0.063 W, AEC-Q200 Grade 0, 0402; Manufacturer: Vishay-Dale; Power_W: 63mW; TempCo: 100 ppm/C; Value_Code: 49R9; Value: 49.9; EIA_Code: E96; SizeX_mm: 1; SizeY_mm: 0.5; SizeZ_mm: 0.6; Value2: 0.063W; AEC Qualified: Y; VDC_V: 50V; AEC Category: Q200; AEC Grade: 0
R41 R156 = CMP-0026822-3: as R40 on sheet FE1_IO
R42 R155 = CMP-0026244-2: as R157 on sheet FE1_IO
R45 = CMP-0025884-3: as R44 on sheet FE1_IO
R53 R159 R164 R165 R180 = CMP-0025958-3: as R56 on sheet FE1_IO
R59 R176 R190 = CMP-0025958-3: as R179 on sheet FE1_IO
R178 R186 R191 R192 R196 R197 = CMP-0026825-4: as R171-R174 on sheet FE1_IO
TP23-TP25 TP29 TP30 TP33 TP34 TP36 TP37 TP40 = CMP-0003719-1: as TP20-TP22 on sheet FE1_IO
U6#2 = CMP-0082537-1: as U5#2 on sheet FE1_IO

## Sheet 2CAN.SchDoc: CAN Interface
size 431 x 279 mm; Date: Not shown in title block; ApprovedBy: Not shown in title block; CheckedBy: Not shown in title block; Author: Not shown in title block; CompanyName: Not shown in title block; DrawnBy: B. Shaffer; Engineer: Not shown in title block; Organization: Not shown in title block; Address1: Not shown in title block; Address2: Not shown in title block; Address3: Not shown in title block; Address4: Not shown in title block; DocumentNumber: 10; Revision: Use project parameter SCH_Rev; SheetNumber: 10; SheetTotal: 17; PageSetup: Record=PageOptions¦CenterHorizontal=True¦CenterVertical=True¦PrintScale=1.00¦XCorrection=1.00¦YCorrection=1.00¦PrintKind=0¦BorderSize=5000000¦LeftOffset=0¦BottomOffset=0¦Orientation=2¦PaperLength=1000¦PaperWidth=1000¦Scale=100¦PaperSource=15¦PrintQuality=600¦MediaType=1¦DitherType=10¦PaperKind=Letter¦PrintScaleMode=1
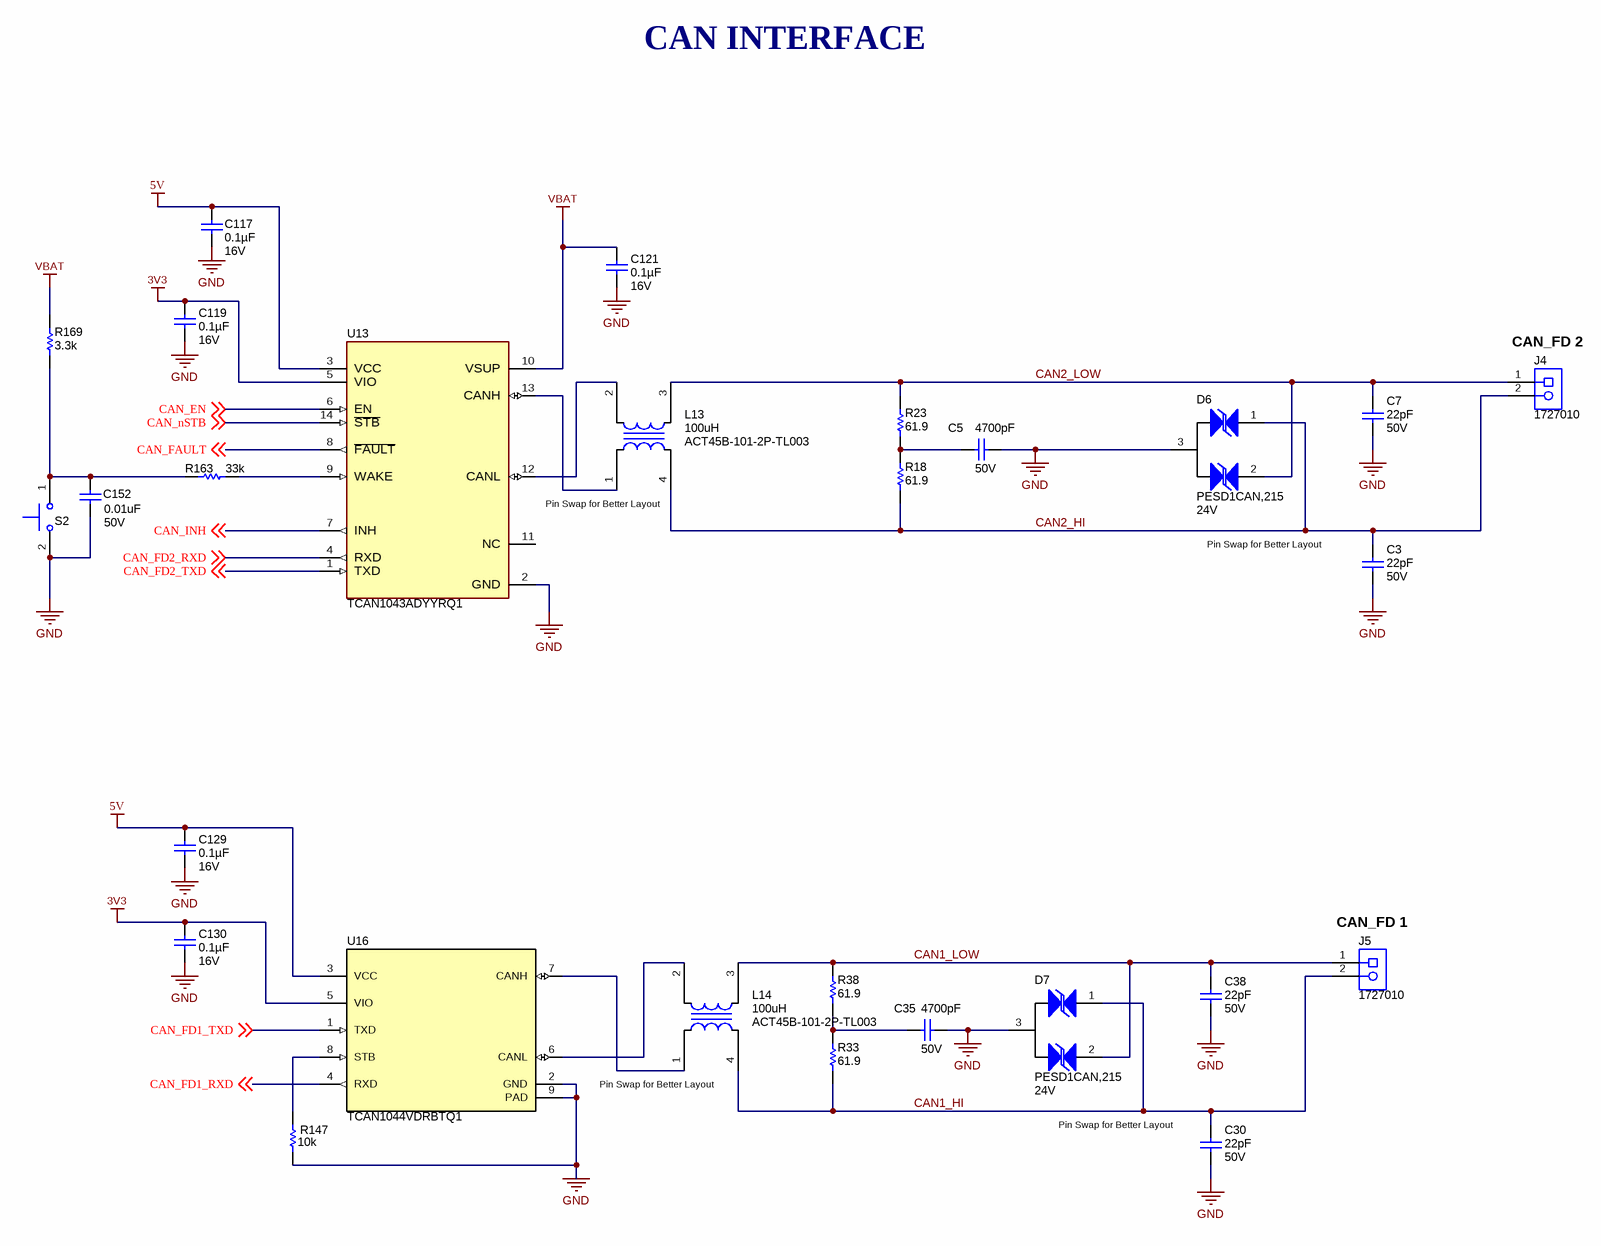
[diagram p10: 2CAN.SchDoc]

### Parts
C3  VDC_V: 50V  ValueDisplayed: 22pF  [0402]  (hidden comment: GRM1555C1H220FA01D)
C5  VDC_V: 50V  ValueDisplayed: 4700pF  [0603]  (hidden comment: GCM188R71H472KA37D)
C7  VDC_V: 50V  ValueDisplayed: 22pF  [0402]  (hidden comment: GRM1555C1H220FA01D)
C30  VDC_V: 50V  ValueDisplayed: 22pF  [0402]  (hidden comment: GRM1555C1H220FA01D)
C35  VDC_V: 50V  ValueDisplayed: 4700pF  [0603]  (hidden comment: GCM188R71H472KA37D)
C38  VDC_V: 50V  ValueDisplayed: 22pF  [0402]  (hidden comment: GRM1555C1H220FA01D)
C117  ValueDisplayed: 0.1µF  Value2: 16V  [0402S]  (hidden comment: 0402YC104KAT2A)
C119  ValueDisplayed: 0.1µF  Value2: 16V  [0402S]  (hidden comment: 0402YC104KAT2A)
C121  ValueDisplayed: 0.1µF  Value2: 16V  [0402S]  (hidden comment: 0402YC104KAT2A)
C129  ValueDisplayed: 0.1µF  Value2: 16V  [0402S]  (hidden comment: 0402YC104KAT2A)
C130  ValueDisplayed: 0.1µF  Value2: 16V  [0402S]  (hidden comment: 0402YC104KAT2A)
C152  VDC_V: 50V  ValueDisplayed: 0.01uF  [0603]  (hidden comment: GRM188R71H103KA01D)
D6  PESD1CAN,215  value 24V  [SOT-23]
D7  PESD1CAN,215  value 24V  [SOT-23]
J4  1727010  [PhoenixConact_1727010]
J5  1727010  [PhoenixConact_1727010]
L13  ValueDisplayed: 100uH  [ACT45B]  (hidden comment: ACT45B-101-2P-TL003)
L14  ValueDisplayed: 100uH  [ACT45B]  (hidden comment: ACT45B-101-2P-TL003)
R18  ValueDisplayed: 61.9  [0402]  (hidden comment: CRCW040261R9FKED)
R23  ValueDisplayed: 61.9  [0402]  (hidden comment: CRCW040261R9FKED)
R33  ValueDisplayed: 61.9  [0402]  (hidden comment: CRCW040261R9FKED)
R38  ValueDisplayed: 61.9  [0402]  (hidden comment: CRCW040261R9FKED)
R147  ValueDisplayed: 10k  [0402]  (hidden comment: CRCW040210K0JNED)
R163  ValueDisplayed: 33k  [0402]  (hidden comment: CRCW040233K0JNED)
R169  ValueDisplayed: 3.3k  [0402]  (hidden comment: CRCW04023K30JNED)
S2  SKRKAEE010  [SW_SKRKAEE010]  (value not drawn)
U13  TCAN1043ADYYRQ1  [DYY0014A-MFG]
U16  TCAN1044VDRBTQ1  [DRB0008J]

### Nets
3V3: C119.1 C130.1 U13.5(VIO) U16.5(VIO)
5V: C117.1 C129.1 U13.3(VCC) U16.3(VCC)
GND: C3.2 C5.1 C7.2 C30.2 C35.1 C38.2 C117.2 C119.2 C121.2 C129.2 C130.2 C152.2 D6.3 D7.3 R147.1 S2.2 U13.2(GND) U16.2(GND) U16.9(PAD)
VBAT: C121.1 R169.2 U13.10(VSUP)
CAN1_HI: C30.1 D7.1 J5.2 L14.4 R33.1
CAN1_LOW: C38.1 D7.2 J5.1 L14.3 R38.2
CAN2_HI: C3.1 D6.1 J4.2 L13.4 R18.1
CAN2_LOW: C7.1 D6.2 J4.1 L13.3 R23.2
CAN_EN: U13.6(EN) ; off-sheet CAN_EN
CAN_FAULT: U13.8(~{FAULT}) ; off-sheet CAN_FAULT
CAN_FD1_RXD: U16.4(RXD) ; off-sheet CAN_FD1_RXD
CAN_FD1_TXD: U16.1(TXD) ; off-sheet CAN_FD1_TXD
CAN_FD2_RXD: U13.4(RXD) ; off-sheet CAN_FD2_RXD
CAN_FD2_TXD: U13.1(TXD) ; off-sheet CAN_FD2_TXD
CAN_INH: U13.7(INH) ; off-sheet CAN_INH
CAN_nSTB: U13.14(~{STB}) ; off-sheet CAN_nSTB
NetC5_2: C5.2 R18.2 R23.1
NetC35_2: C35.2 R33.2 R38.1
NetC152_1: C152.1 R163.1 R169.1 S2.1
NetL13_1: L13.1 U13.13(CANH)
NetL13_2: L13.2 U13.12(CANL)
NetL14_1: L14.1 U16.7(CANH)
NetL14_2: L14.2 U16.6(CANL)
NetR147_2: R147.2 U16.8(STB)
NetR163_2: R163.2 U13.9(WAKE)

Not connected (* = marked no-connect by the designer): U13 11(NC)

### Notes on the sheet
- CAN INTERFACE
- (near J4) CAN_FD 2
- Pin Swap for Better Layout
- (near J5) CAN_FD 1
- (near L14) Pin Swap for Better Layout
- (near C30) Pin Swap for Better Layout

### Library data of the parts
C3 C7 C30 C38 = CMP-0006438-2: CAP, CERM, 22 pF, 50 V, +/- 1%, C0G/NP0, 0402; Manufacturer: MuRata; TaMin_C: -55°C; Polarized: N; SizeAreaWB_mm2: 3; Value1: Unknown; U/M: EA; Value: 22pF; TaMax_C: 125°C; SizeZ_mm: 0.6; SizeX_mm: 1; SizeY_mm: 0.5; CompType: Capacitor; AEC Category: Q200
C5 C35 = CMP-0007146-2: CAP, CERM, 4700 pF, 50 V, +/- 10%, X7R, AEC-Q200 Grade 1, 0603; Manufacturer: MuRata; TaMin_C: -55°C; Polarized: N; SizeAreaWB_mm2: 4.68; Value1: Unknown; U/M: EA; Value: 4700pF; TaMax_C: 125°C; SizeZ_mm: 1; SizeX_mm: 1.6; SizeY_mm: 0.8; SizeArea_mm2: 1.28; AEC Qualified: Y; Cap_F: 4.7nF; AEC Category: Q200
C117 C119 C121 C129 C130 = 0402YC104KAT2A: CAP, CERM, 0.1 µF, 16 V, +/- 10%, X7R, 0402; Manufacturer: AVX; Polarized: N; CompType: Capacitor; Value: 0.1uF; U/M: EA; Cap_F: 0.0000001; Tolerance_%: 10; Value1: Unknown; VDC_V: 16; TaMin_C: -55; TaMax_C: 125; Cap_Case: 0402; SizeArea_mm2: 0.5; SizeAreaWB_mm2: 3; SizeX_mm: 1; SizeZ_mm: 0.6; AEC Category: Q200
C152 = CMP-0007433-4: CAP, CERM, 0.01 uF, 50 V, +/- 10%, X7R, 0603; Manufacturer: MuRata; TaMin_C: -55°C; Polarized: N; SizeAreaWB_mm2: 4.68; Value1: Unknown; U/M: EA; Value: 0.01uF; TaMax_C: 125°C; SizeZ_mm: 1; SizeX_mm: 1.6; SizeY_mm: 0.8; SizeArea_mm2: 1.28; Cap_F: 10nF; AEC Category: Q200
D6 D7 = CMP-0005920-3: Diode, TVS, Bi, 24 V, 70 Vc, AEC-Q101, SOT-23; Manufacturer: NXP Semiconductor; SizeArea_mm2: 7.5; AEC Category: Q101; Ppk: 200W; Ipp: 3A; Vbr_Min: 25.4V; SizeZ_mm: 1.1; AEC Qualified: Y; Vc: 70V; SizeX_mm: 2.5; SizeY_mm: 3; SizeAreaWB_mm2: 14; Vbr_Max: 30.3V
J4 J5 = CMP-0055472-1: Conn Term Block, 2POS, 3.81mm, TH; Manufacturer: Phoenix Contact; CT: TRUE; Green_REACh: Incomplete; CompType: Terminal Block; CNHeader: FALSE; Green_Lifecycle: Not Set
L13 L14 = CMP-0062430-2: Inductor, Ferrite, 100 uH, 0.15 A, 2 ohm, SMD; Manufacturer: TDK; Isat: 0.15A @ % inductance drop; Green_Lifecycle: Active; SizeAreaWB_mm2: 23.1; DCR_ohm: 2; Green_REACh: Passed; Value1: 2 ohm; Value: 100uH; Imax_A: 1.5dA; SizeZ_mm: 3; SizeX_mm: 4.5; SizeY_mm: 3.2; Value2: 0.15A; SizeArea_mm2: 14.4; Ind_H: 100µH; AEC Category: Q200
R18 R23 R33 R38 = CMP-0026491-1: RES, 61.9, 1%, 0.063 W, 0402; Manufacturer: Vishay-Dale; Power_W: 63mW; TempCo: 100 ppm/C; Value_Code: 61R9; U/M: EA; Value: 61.9; EIA_Code: E96; SizeX_mm: 1; SizeY_mm: 0.5; SizeZ_mm: 0.6; Value2: 0.063W; VDC_V: 50V; AEC Category: Q200
R147 = CRCW040210K0JNED: RES, 10 k, 5%, 0.063 W, 0402; Manufacturer: Vishay-Dale; CompType: Resistor; Value: 10k; Res_ohm: 10000; Value_Code: 10k0; Tolerance_%: 5; Power_W: 0.063; Value2: 0.063W; VDC_V: 50; TempCo: 200 ppm/C; SizeArea_mm2: 0.5; SizeX_mm: 1; SizeZ_mm: 0.6; EIA_Code: E24; U/M: EA; AEC Category: Q200
R163 = CMP-0026907-3: RES, 33 k, 5%, 0.063 W, AEC-Q200 Grade 0, 0402; Manufacturer: Vishay-Dale; Power_W: 63mW; TempCo: 200 ppm/C; Value_Code: 33k0; Value: 33k; EIA_Code: E24; SizeX_mm: 1; SizeY_mm: 0.5; SizeZ_mm: 0.6; Value2: 0.063W; AEC Qualified: Y; VDC_V: 50V; AEC Category: Q200; AEC Grade: 0
R169 = CMP-0026918-5: RES, 3.3 k, 5%, 0.063 W, AEC-Q200 Grade 0, 0402; Manufacturer: Vishay-Dale; Power_W: 63mW; TempCo: 200 ppm/C; Value_Code: 3k30; Value: 3.3k; EIA_Code: E24; SizeX_mm: 1; SizeY_mm: 0.5; SizeZ_mm: 0.6; Value2: 0.063W; AEC Qualified: Y; VDC_V: 50V; AEC Category: Q200; AEC Grade: 0
S2 = SKRKAEE010: Switch, Tactile, 12v, 50mA, Vertical, SMD; Manufacturer: Alps; Alternate Manufacturer: Any; Alternate PartNumber: Equivalent; SymbolCreator: a0412235; Circuit: SPST-NO; VDC_V: 12; SwitchFunction: Off-Mom; PositionCount: 1; CurrentRating_mA: 50; EN: 205-1-00046; Mfg: ALPS ELECTRIC CO., LTD; Onhand: 0
U13 = CMP-0089855-1: Low-Power Fault Protected CAN FD Transceiver with INH and WAKE; Manufacturer: Texas Instruments; Max Supply Voltage: 28V; Standoff Height: 0mm; Min Supply Voltage: 1.7V; AEC Grade: Grade 1; SizeZ_mm: 1.1mm; TJmax_C: +165°C; AEC Qualified: Yes
U16 = CMP-0079884-2: Automotive High Speed CAN Transceiver, DRB0008J (VSON-8); Alternate Manufacturer: Texas Instruments; Alternate PartNumber: TCAN1044VDRBRQ1; SizeX_mm: 3; AEC Category: Q200; SizeAreaWB_mm2: 16; SizeZ_mm: 1; SizeArea_mm2: 9; AEC Qualified: Y; CompType: IC

## Sheet Enet_PHY.SchDoc
size 431 x 279 mm; Date: Not shown in title block; ApprovedBy: Not shown in title block; CheckedBy: Not shown in title block; Author: Not shown in title block; CompanyName: Not shown in title block; DrawnBy: B. Shaffer; Engineer: Not shown in title block; Organization: Not shown in title block; Address1: Not shown in title block; Address2: Not shown in title block; Address3: Not shown in title block; Address4: Not shown in title block; DocumentNumber: 11; Revision: Use project parameter SCH_Rev; SheetNumber: 11; SheetTotal: 17; PageSetup: Record=PageOptions¦CenterHorizontal=True¦CenterVertical=True¦PrintScale=1.00¦XCorrection=1.00¦YCorrection=1.00¦PrintKind=0¦BorderSize=5000000¦LeftOffset=0¦BottomOffset=0¦Orientation=2¦PaperLength=1000¦PaperWidth=1000¦Scale=100¦PaperSource=15¦PrintQuality=600¦MediaType=1¦DitherType=10¦PaperKind=Letter¦PrintScaleMode=1
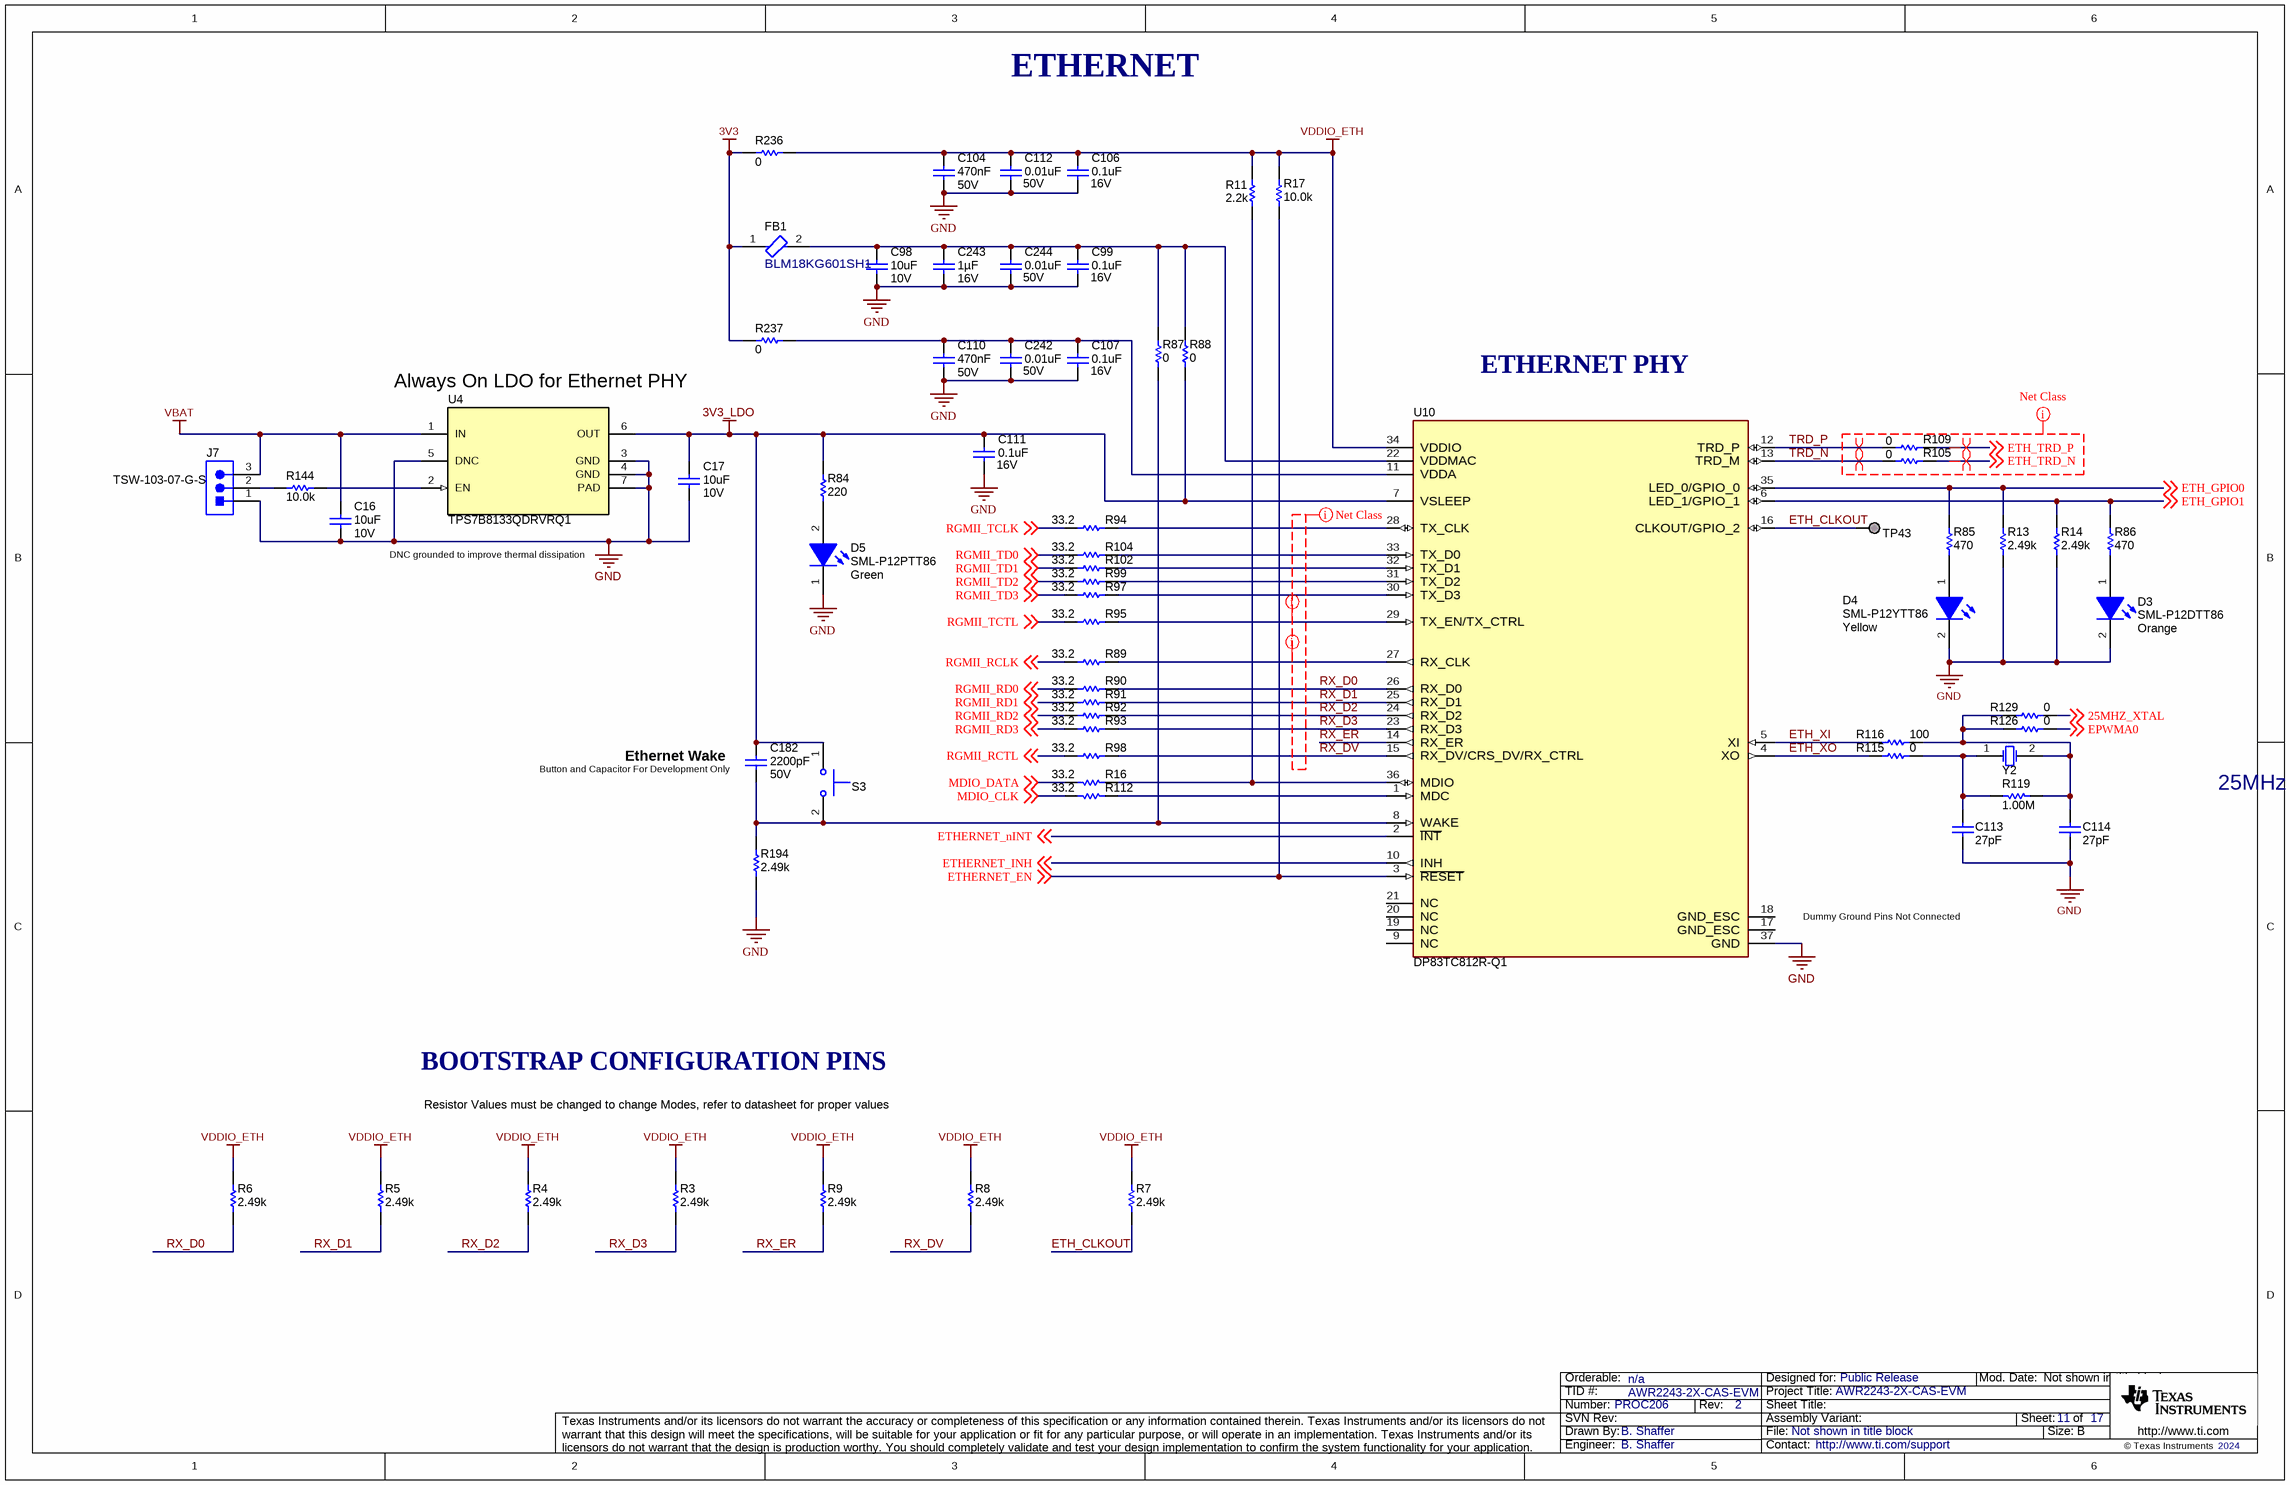
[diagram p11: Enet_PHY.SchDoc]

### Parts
C16  VDC_V: 10V  ValueDisplayed: 10uF  [0805_HV]  (hidden comment: GCM21BR71A106KE22L)
C17  VDC_V: 10V  ValueDisplayed: 10uF  [0805_HV]  (hidden comment: GCM21BR71A106KE22L)
C98  VDC_V: 10V  ValueDisplayed: 10uF  [0805_HV]  (hidden comment: GCM21BR71A106KE22L)
C99  VDC_V: 16V  ValueDisplayed: 0.1uF  [0402L]  (hidden comment: GCM155R71C104KA55D)
C104  Cap_F: 470nF  VDC_V: 50V  [0603]  (hidden comment: CGA3E3X7R1H474K080AE)
C106  VDC_V: 16V  ValueDisplayed: 0.1uF  [0402L]  (hidden comment: GCM155R71C104KA55D)
C107  VDC_V: 16V  ValueDisplayed: 0.1uF  [0402L]  (hidden comment: GCM155R71C104KA55D)
C110  Cap_F: 470nF  VDC_V: 50V  [0603]  (hidden comment: CGA3E3X7R1H474K080AE)
C111  VDC_V: 16V  ValueDisplayed: 0.1uF  [0402L]  (hidden comment: GCM155R71C104KA55D)
C112  VDC_V: 50V  ValueDisplayed: 0.01uF  [0402]  (hidden comment: CGA2B3X7R1H103K050BB)
C113  ValueDisplayed: 27pF  [0402]  (hidden comment: GCM1555C1H270JA16D)
C114  ValueDisplayed: 27pF  [0402]  (hidden comment: GCM1555C1H270JA16D)
C182  value 2200pF  VDC_V: 50V  [0402]  (hidden comment: UMK105B7222KV-F)
C242  VDC_V: 50V  ValueDisplayed: 0.01uF  [0402]  (hidden comment: CGA2B3X7R1H103K050BB)
C243  VDC_V: 16V  ValueDisplayed: 1µF  [0603S]  (hidden comment: GCM188R71C105KA64J)
C244  VDC_V: 50V  ValueDisplayed: 0.01uF  [0402]  (hidden comment: CGA2B3X7R1H103K050BB)
D3  SML-P12DTT86  value Orange  [LED_SMLP12_ORANGE]
D4  SML-P12YTT86  value Yellow  [LED_SMLP12_YELLOW]
D5  SML-P12PTT86  value Green  [SML-P1_GREEN]
FB1  BLM18KG601SH1  [FP-BLM18KG601SH1_0603 (1608 Metric)-MFG]
J7  TSW-103-07-G-S  [TSW-103-07-X-S]
R3  ValueDisplayed: 2.49k  [0402]  (hidden comment: CRCW04022K49FKED)
R4  ValueDisplayed: 2.49k  [0402]  (hidden comment: CRCW04022K49FKED)
R5  ValueDisplayed: 2.49k  [0402]  (hidden comment: CRCW04022K49FKED)
R6  ValueDisplayed: 2.49k  [0402]  (hidden comment: CRCW04022K49FKED)
R7  ValueDisplayed: 2.49k  [0402]  (hidden comment: CRCW04022K49FKED)
R8  ValueDisplayed: 2.49k  [0402]  (hidden comment: CRCW04022K49FKED)
R9  ValueDisplayed: 2.49k  [0402]  (hidden comment: CRCW04022K49FKED)
R11  ValueDisplayed: 2.2k  [0402]  (hidden comment: CRCW04022K20JNED)
R13  ValueDisplayed: 2.49k  [0402]  (hidden comment: CRCW04022K49FKED)
R14  ValueDisplayed: 2.49k  [0402]  (hidden comment: CRCW04022K49FKED)
R16  ValueDisplayed: 33.2  [0201_Silk]  (hidden comment: CRCW020133R2FNED)
R17  ValueDisplayed: 10.0k  [0402L]  (hidden comment: CRCW040210K0FKED)
R84  ValueDisplayed: 220  [0402]  (hidden comment: ERJ-2RKF2200X)
R85  ValueDisplayed: 470  [0402]  (hidden comment: ERJ-2RKF4700X)
R86  ValueDisplayed: 470  [0402]  (hidden comment: ERJ-2RKF4700X)
R87  ValueDisplayed: 0  [0402]  (hidden comment: CRCW04020000Z0ED)
R88  ValueDisplayed: 0  [0402]  (hidden comment: CRCW04020000Z0ED)
R89  ValueDisplayed: 33.2  [0201]  (hidden comment: CRCW020133R2FNED)
R90  ValueDisplayed: 33.2  [0201]  (hidden comment: CRCW020133R2FNED)
R91  ValueDisplayed: 33.2  [0201]  (hidden comment: CRCW020133R2FNED)
R92  ValueDisplayed: 33.2  [0201]  (hidden comment: CRCW020133R2FNED)
R93  ValueDisplayed: 33.2  [0201]  (hidden comment: CRCW020133R2FNED)
R94  ValueDisplayed: 33.2  [0201]  (hidden comment: CRCW020133R2FNED)
R95  ValueDisplayed: 33.2  [0201]  (hidden comment: CRCW020133R2FNED)
R97  ValueDisplayed: 33.2  [0201]  (hidden comment: CRCW020133R2FNED)
R98  ValueDisplayed: 33.2  [0201]  (hidden comment: CRCW020133R2FNED)
R99  ValueDisplayed: 33.2  [0201]  (hidden comment: CRCW020133R2FNED)
R102  ValueDisplayed: 33.2  [0201]  (hidden comment: CRCW020133R2FNED)
R104  ValueDisplayed: 33.2  [0201]  (hidden comment: CRCW020133R2FNED)
R105  ValueDisplayed: 0  [0201_Silk]  (hidden comment: CRCW02010000Z0ED)
R109  ValueDisplayed: 0  [0201_Silk]  (hidden comment: CRCW02010000Z0ED)
R112  ValueDisplayed: 33.2  [0201_Silk]  (hidden comment: CRCW020133R2FNED)
R115  ValueDisplayed: 0  [0402]  (hidden comment: CRCW04020000Z0ED)
R116  ValueDisplayed: 100  [0402]  (hidden comment: CRCW0402100RJNED)
R119  ValueDisplayed: 1.00M  [0603]  (hidden comment: CRCW06031M00FKEA)
R126  ValueDisplayed: 0  [0402]  (hidden comment: CRCW04020000Z0ED)
R129  ValueDisplayed: 0  [0402]  (hidden comment: CRCW04020000Z0ED)
R144  ValueDisplayed: 10.0k  [0402L]  (hidden comment: CRCW040210K0FKED)
R194  ValueDisplayed: 2.49k  [0402]  (hidden comment: CRCW04022K49FKED)
R236  ValueDisplayed: 0  [0603]  (hidden comment: RMCF0603ZT0R00)
R237  ValueDisplayed: 0  [0603]  (hidden comment: RMCF0603ZT0R00)
S3  SKRKAEE010  [SW_SKRKAEE010]  (value not drawn)
TP43  TP_H0.45P0.75  [TP_H045P075]  (value not drawn)  (no BOM)
U4  TPS7B8133QDRVRQ1  [DRV0006A]
U10  DP83TC812R-Q1  [RHA0036A-MFG]
Y2  ABM3-25.000MHZ-D2W-T  [XTAL_ABM3]  (value not drawn)

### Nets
3V3: FB1.1 R236.1 R237.1
3V3_LDO: C17.1 C111.2 C182.1 R84.2 R88.2 S3.1 U4.6(OUT) U10.7(VSLEEP)
GND: C16.2 C17.2 C98.2 C99.1 C104.2 C106.1 C107.1 C110.2 C111.1 C112.2 C113.2 C114.2 C242.2 C243.2 C244.2 D3.2(K) D4.2(K) D5.1(K) J7.1 R13.1 R14.2 R194.1 U4.3(GND) U4.4(GND) U4.5(DNC) U4.7(PAD) U10.37(GND)
VBAT: C16.1 J7.3 U4.1(IN)
VDDIO_ETH: C104.1 C106.2 C112.1 R3.2 R4.2 R5.2 R6.2 R7.2 R8.2 R9.2 R11.2 R17.1 R236.2 U10.34(VDDIO)
25MHZ_XTAL: R129.1 ; off-sheet 25MHZ_XTAL
EPWMA0: R126.1 ; off-sheet EPWMA0
ETH_CLKOUT: R7.1 TP43.1 U10.16(CLKOUT/GPIO_2)
ETH_GPIO0: R13.2 R85.2 U10.35(LED_0/GPIO_0) ; off-sheet ETH_GPIO0
ETH_GPIO1: R14.1 R86.2 U10.6(LED_1/GPIO_1) ; off-sheet ETH_GPIO1
ETH_TRD_N: R105.2 ; off-sheet ETH_TRD_N
ETH_TRD_P: R109.2 ; off-sheet ETH_TRD_P
ETH_XI: R116.1 U10.5(XI)
ETH_XO: R115.2 U10.4(XO)
ETHERNET_EN: R17.2 U10.3(~{RESET}) ; off-sheet ETHERNET_EN
ETHERNET_INH: U10.10(INH) ; off-sheet ETHERNET_INH
ETHERNET_nINT: U10.2(~{INT}) ; off-sheet ETHERNET_nINT
MDIO_CLK: R112.1 ; off-sheet MDIO_CLK
MDIO_DATA: R16.1 ; off-sheet MDIO_DATA
RGMII_RCLK: R89.1 ; off-sheet RGMII_RCLK
RGMII_RCTL: R98.1 ; off-sheet RGMII_RCTL
RGMII_RD0: R90.1 ; off-sheet RGMII_RD0
RGMII_RD1: R91.1 ; off-sheet RGMII_RD1
RGMII_RD2: R92.1 ; off-sheet RGMII_RD2
RGMII_RD3: R93.1 ; off-sheet RGMII_RD3
RGMII_TCLK: R94.1 ; off-sheet RGMII_TCLK
RGMII_TCTL: R95.1 ; off-sheet RGMII_TCTL
RGMII_TD0: R104.1 ; off-sheet RGMII_TD0
RGMII_TD1: R102.1 ; off-sheet RGMII_TD1
RGMII_TD2: R99.1 ; off-sheet RGMII_TD2
RGMII_TD3: R97.1 ; off-sheet RGMII_TD3
RX_D0: R6.1 R90.2 U10.26(RX_D0)
RX_D1: R5.1 R91.2 U10.25(RX_D1)
RX_D2: R4.1 R92.2 U10.24(RX_D2)
RX_D3: R3.1 R93.2 U10.23(RX_D3)
RX_DV: R8.1 R98.2 U10.15(RX_DV/CRS_DV/RX_CTRL)
RX_ER: R9.1 U10.14(RX_ER)
TRD_N: R105.1 U10.13(TRD_M)
TRD_P: R109.1 U10.12(TRD_P)
NetC98_1: C98.1 C99.2 C243.1 C244.1 FB1.2 R87.1 R88.1 U10.22(VDDMAC)
NetC107_2: C107.2 C110.1 C242.1 R237.2 U10.11(VDDA)
NetC113_1: C113.1 R115.1 R119.2 Y2.1(OSC1)
NetC114_1: C114.1 R116.2 R119.1 R126.2 R129.2 Y2.2(OSC2)
NetC182_2: C182.2 R87.2 R194.2 S3.2 U10.8(WAKE)
NetD3_1: D3.1(A) R86.1
NetD4_1: D4.1(A) R85.1
NetD5_2: D5.2(A) R84.1
NetJ7_2: J7.2 R144.1
NetR11_1: R11.1 R16.2 U10.36(MDIO)
NetR89_2: R89.2 U10.27(RX_CLK)
NetR94_2: R94.2 U10.28(TX_CLK)
NetR95_2: R95.2 U10.29(TX_EN/TX_CTRL)
NetR97_2: R97.2 U10.30(TX_D3)
NetR99_2: R99.2 U10.31(TX_D2)
NetR102_2: R102.2 U10.32(TX_D1)
NetR104_2: R104.2 U10.33(TX_D0)
NetR112_2: R112.2 U10.1(MDC)
NetR144_2: R144.2 U4.2(EN)

Not connected (* = marked no-connect by the designer): U10 9(NC) 17(GND_ESC) 18(GND_ESC) 19(NC) 20(NC) 21(NC)

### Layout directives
net class RGMII: (no net found under the mark), ETH_TRD_N, ETH_TRD_P, NetR89_2, NetR95_2
differential pair: ETH_TRD_N, ETH_TRD_P, TRD_N, TRD_P

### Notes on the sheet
- ETHERNET
- (near U4) Always On LDO for Ethernet PHY
- ETHERNET PHY
- DNC grounded to improve thermal dissipation
- (near C182) Button and Capacitor For Development Only
- (near C182) Ethernet Wake
- (near C114) 25MHz XTAL
- Dummy Ground Pins Not Connected
- BOOTSTRAP CONFIGURATION PINS
- Resistor Values must be changed to change Modes, refer to datasheet for proper values

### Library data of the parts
C16 C17 C98 = CMP-0008017-2: as C40 on sheet FE1_IO
C99 C106 C107 C111 = CMP-0006351-2: as C175 on sheet FE2_PWR
C104 C110 = CMP-0007097-4: CAP, CERM, 0.47 uF, 50 V, +/- 10%, X7R, AEC-Q200 Grade 1, 0603; Manufacturer: TDK; TaMin_C: -55°C; Polarized: N; SizeAreaWB_mm2: 4.68; Value1: Unknown; U/M: EA; Value: 0.47uF; TaMax_C: 125°C; SizeZ_mm: 1; SizeX_mm: 1.6; SizeY_mm: 0.8; SizeArea_mm2: 1.28; AEC Qualified: Y; AEC Category: Q200
C112 C242 C244 = CMP-0006324-2: CAP, CERM, 0.01 uF, 50 V, +/- 10%, X7R, AEC-Q200 Grade 1, 0402; Manufacturer: TDK; TaMin_C: -55°C; ESR_ohm: 0.333065; Polarized: N; SizeAreaWB_mm2: 3; Value1: 0.333065 ohm; U/M: EA; Value: 0.01uF; TaMax_C: 125°C; SizeZ_mm: 0.6; SizeX_mm: 1; SizeY_mm: 0.5; CompType: Capacitor; AEC Qualified: Y; Cap_F: 10nF; IRMS_A: 323.373mA; AEC Category: Q200
C113 C114 = CMP-0860920-1: CAP, CERM, 27 pF, 50 V,+/- 5%, C0G/NP0, AEC-Q200 Grade 1, 0402; Manufacturer: MuRata; AEC Grade: 1; SizeZ_mm: 0.6; U/M: EA; Value: 27pF; SizeY_mm: 0.5; TaMax_C: 125°C; Polarized: N; AEC Qualified: Y; AEC Category: Q200; Value2: 50V; SizeAreaWB_mm2: 3; TaMin_C: -55°C
C182 = Capacitor: Cap, Cer-X7R, 2200pF, 50V, 10%, 0402; Manufacturer: Taiyo Yuden; PART Name: SCH_LIB\CAP_NP; Polarized: N; U/M: EA; TempCo: X7R; DECAL Name: 0402,0402_HD; EN: 102-1-00062; Onhand: 7818
C243 = CMP-0079154-1: as C186 on sheet FE2_PWR
D3 = CMP-0002841-1: LED, Orange, SMD; Manufacturer: Rohm; Io_A: 20mA; Tjmax_C: 85°C; Value1: W; U/M: EA; Vf_V: 2.1V; Type: InGaN
D4 = CMP-0002839-2: LED, Yellow, SMD; Manufacturer: Rohm; Vf_V: 2.1V; Tjmax_C: 85°C; Value1: W; Type: InGaN; Io_A: 20mA
D5 = CMP-0002873-2: LED, Green, SMD; Manufacturer: Rohm; Value1: W; Type: AlInGaP; Value2: 2.2V; Io_A: 20mA
FB1 = CMP-0089848-1: 600 Ohms @ 100MHz 1 Power Line Ferrite Bead 0603 (1608 Metric) 1.3A 150mOhm; Manufacturer: Murata; Tolerance_%: 25%; SizeZ_mm: 0.95mm; Impedance At Frequency: 600Ω @ 100MHz; AEC Qualified: Yes; AEC Grade: Grade 1; DCR_ohm: 1.5d
J7 = CMP-0075407-1: Header, 100mil, 3x1, Gold, TH; Manufacturer: Samtec; Pitch_mm: 2.54; Cert_VDE: N; Gender: Male; Cert_CSA: Y; Voltage_V: 550V; Green_REACh: Passed; Current_A: 6.3A; CT: False; Green_Lifecycle: Active; Row_Count: 1; CNHeader: True
R3-R9 R13 R14 R194 = CMP-0026237-2: RES, 2.49 k, 1%, 0.063 W, AEC-Q200 Grade 0, 0402; Manufacturer: Vishay-Dale; Power_W: 63mW; TempCo: 100 ppm/C; Value_Code: 2k49; Value: 2.49k; EIA_Code: E96; SizeX_mm: 1; SizeY_mm: 0.5; SizeZ_mm: 0.6; Value2: 0.063W; AEC Qualified: Y; VDC_V: 50V; AEC Category: Q200; AEC Grade: 0
R11 = CMP-0026890-5: RES, 2.2 k, 5%, 0.063 W, AEC-Q200 Grade 0, 0402; Manufacturer: Vishay-Dale; Power_W: 63mW; TempCo: 200 ppm/C; Value_Code: 2k20; Value: 2.2k; EIA_Code: E24; SizeX_mm: 1; SizeY_mm: 0.5; SizeZ_mm: 0.6; Value2: 0.063W; AEC Qualified: Y; VDC_V: 50V; AEC Category: Q200; AEC Grade: 0
R16 R89-R95 R97-R99 R102 R104 R112 = CMP-0027275-3: RES, 33.2, 1%, 0.05 W, 0201; Manufacturer: Vishay-Dale; Power_W: 50mW; TempCo: 200 ppm/C; Value_Code: 33R2; Value: 33.2; EIA_Code: E96; SizeX_mm: 0.6; SizeY_mm: 0.3; SizeZ_mm: 0.26; Value2: 0.05W; SizeArea_mm2: 0.18; AEC Qualified: N; AEC Category: Q200
R17 = CMP-0025958-3: as R179 on sheet FE1_IO
R84 = CMP-0026680-1: RES, 220, 1%, 0.1 W, AEC-Q200 Grade 0, 0402; Manufacturer: Panasonic; Power_W: 100mW; TempCo: 100 ppm/C; Value_Code: 220R; U/M: EA; Value: 220; SizeX_mm: 1; SizeY_mm: 0.5; SizeZ_mm: 0.6; Value2: 0.1W; AEC Qualified: Y; VDC_V: 50V; AEC Grade: 0; AEC Category: Q200
R85 R86 = CMP-0026699-1: RES, 470, 1%, 0.1 W, AEC-Q200 Grade 0, 0402; Manufacturer: Panasonic; Power_W: 100mW; TempCo: 100 ppm/C; Value_Code: 470R; U/M: EA; Value: 470; SizeX_mm: 1; SizeY_mm: 0.5; SizeZ_mm: 0.6; Value2: 0.1W; AEC Qualified: Y; VDC_V: 50V; AEC Grade: 0; AEC Category: Q200
R87 R88 R115 R129 = CMP-0026822-3: as R40 on sheet FE1_IO
R105 R109 = CMP-0027008-4: RES, 0, 5%, 0.05 W, 0201; Manufacturer: Vishay-Dale; Power_W: 50mW; TempCo: ppm/C; Value_Code: 0000; Value: 0; EIA_Code: E24; SizeX_mm: 0.6; SizeY_mm: 0.3; SizeZ_mm: 0.26; Value2: 0.05W; SizeArea_mm2: 0.18; AEC Qualified: N; AEC Category: Q200
R116 = CMP-0026824-3: RES, 100, 5%, 0.063 W, AEC-Q200 Grade 0, 0402; Manufacturer: Vishay-Dale; Power_W: 63mW; TempCo: 200 ppm/C; Value_Code: 100R; Value: 100; EIA_Code: E24; SizeX_mm: 1; SizeY_mm: 0.5; SizeZ_mm: 0.6; Value2: 0.063W; AEC Qualified: Y; VDC_V: 50V; AEC Category: Q200; AEC Grade: 0
R119 = CMP-0022138-4: RES, 1.00 M, 1%, 0.1 W, AEC-Q200 Grade 0, 0603; Manufacturer: Vishay-Dale; Power_W: 100mW; TempCo: 100 ppm/C; Value_Code: 1M00; Value: 1.00Meg; EIA_Code: E96; Res_ohm: 1M; SizeX_mm: 1.6; SizeY_mm: 0.8; SizeZ_mm: 1; Value2: 0.1W; SizeArea_mm2: 1.28; AEC Qualified: Y; VDC_V: 75V; AEC Category: Q200; AEC Grade: 0
R126 = CMP-0026822-3: RES, 0, 5%, 0.063 W, AEC-Q200 Grade 0, 0402; Manufacturer: Vishay-Dale; Power_W: 63mW; TempCo: 200 ppm/C; Value_Code: 0000; Value: 0; EIA_Code: E24; SizeX_mm: 1; SizeY_mm: 0.5; SizeZ_mm: 0.6; Value2: 0.063W; CompType: Resistor; AEC Qualified: Y; VDC_V: 50V; AEC Category: Q200
R144 = CMP-0025958-3: as R56 on sheet FE1_IO
R236 R237 = CMP-0023343-3: RES, 0, 1%, 0.1 W, AEC-Q200 Grade 0, 0603; Manufacturer: Stackpole Electronics Inc; Power_W: 100mW; TempCo: ppm/C; U/M: EA; Value: 0; SizeX_mm: 1.6; SizeY_mm: 0.8; SizeZ_mm: 1; Value2: 0.1W; SizeArea_mm2: 1.28; AEC Qualified: Y; AEC Category: Q200
S3 = SKRKAEE010: as S2 on sheet 2CAN
TP43 = CMP-0003719-1: as TP20-TP22 on sheet FE1_IO
U4 = CMP-0860463-1: Automotive 150-mA high-voltage ultra-low-IQ low-dropout (LDO) linear regulator, DRV0006A (WSON-6); Alternate Manufacturer: Texas Instruments; AEC Qualified: Y; SizeY_mm: 2; SizeZ_mm: 0.8; AEC Category: Q200; CompType: IC; SizeArea_mm2: 4; SizeAreaWB_mm2: 9
U10 = CMP-0089064-1: TC-10 Compliant 100Base-T1 Automotive Ethernet PHY; Manufacturer: Texas Instruments; SizeZ_mm: 1mm; AEC Qualified: Yes
Y2 = CMP-0004614-3: Crystal, 25 MHz, 18 pF, SMD; Manufacturer: Abracon Corporation; TaMax_C: 85°C; TaMin_C: -40°C; Frequency Stability: +/-25ppm; Frequency_Fixed: 25MHz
